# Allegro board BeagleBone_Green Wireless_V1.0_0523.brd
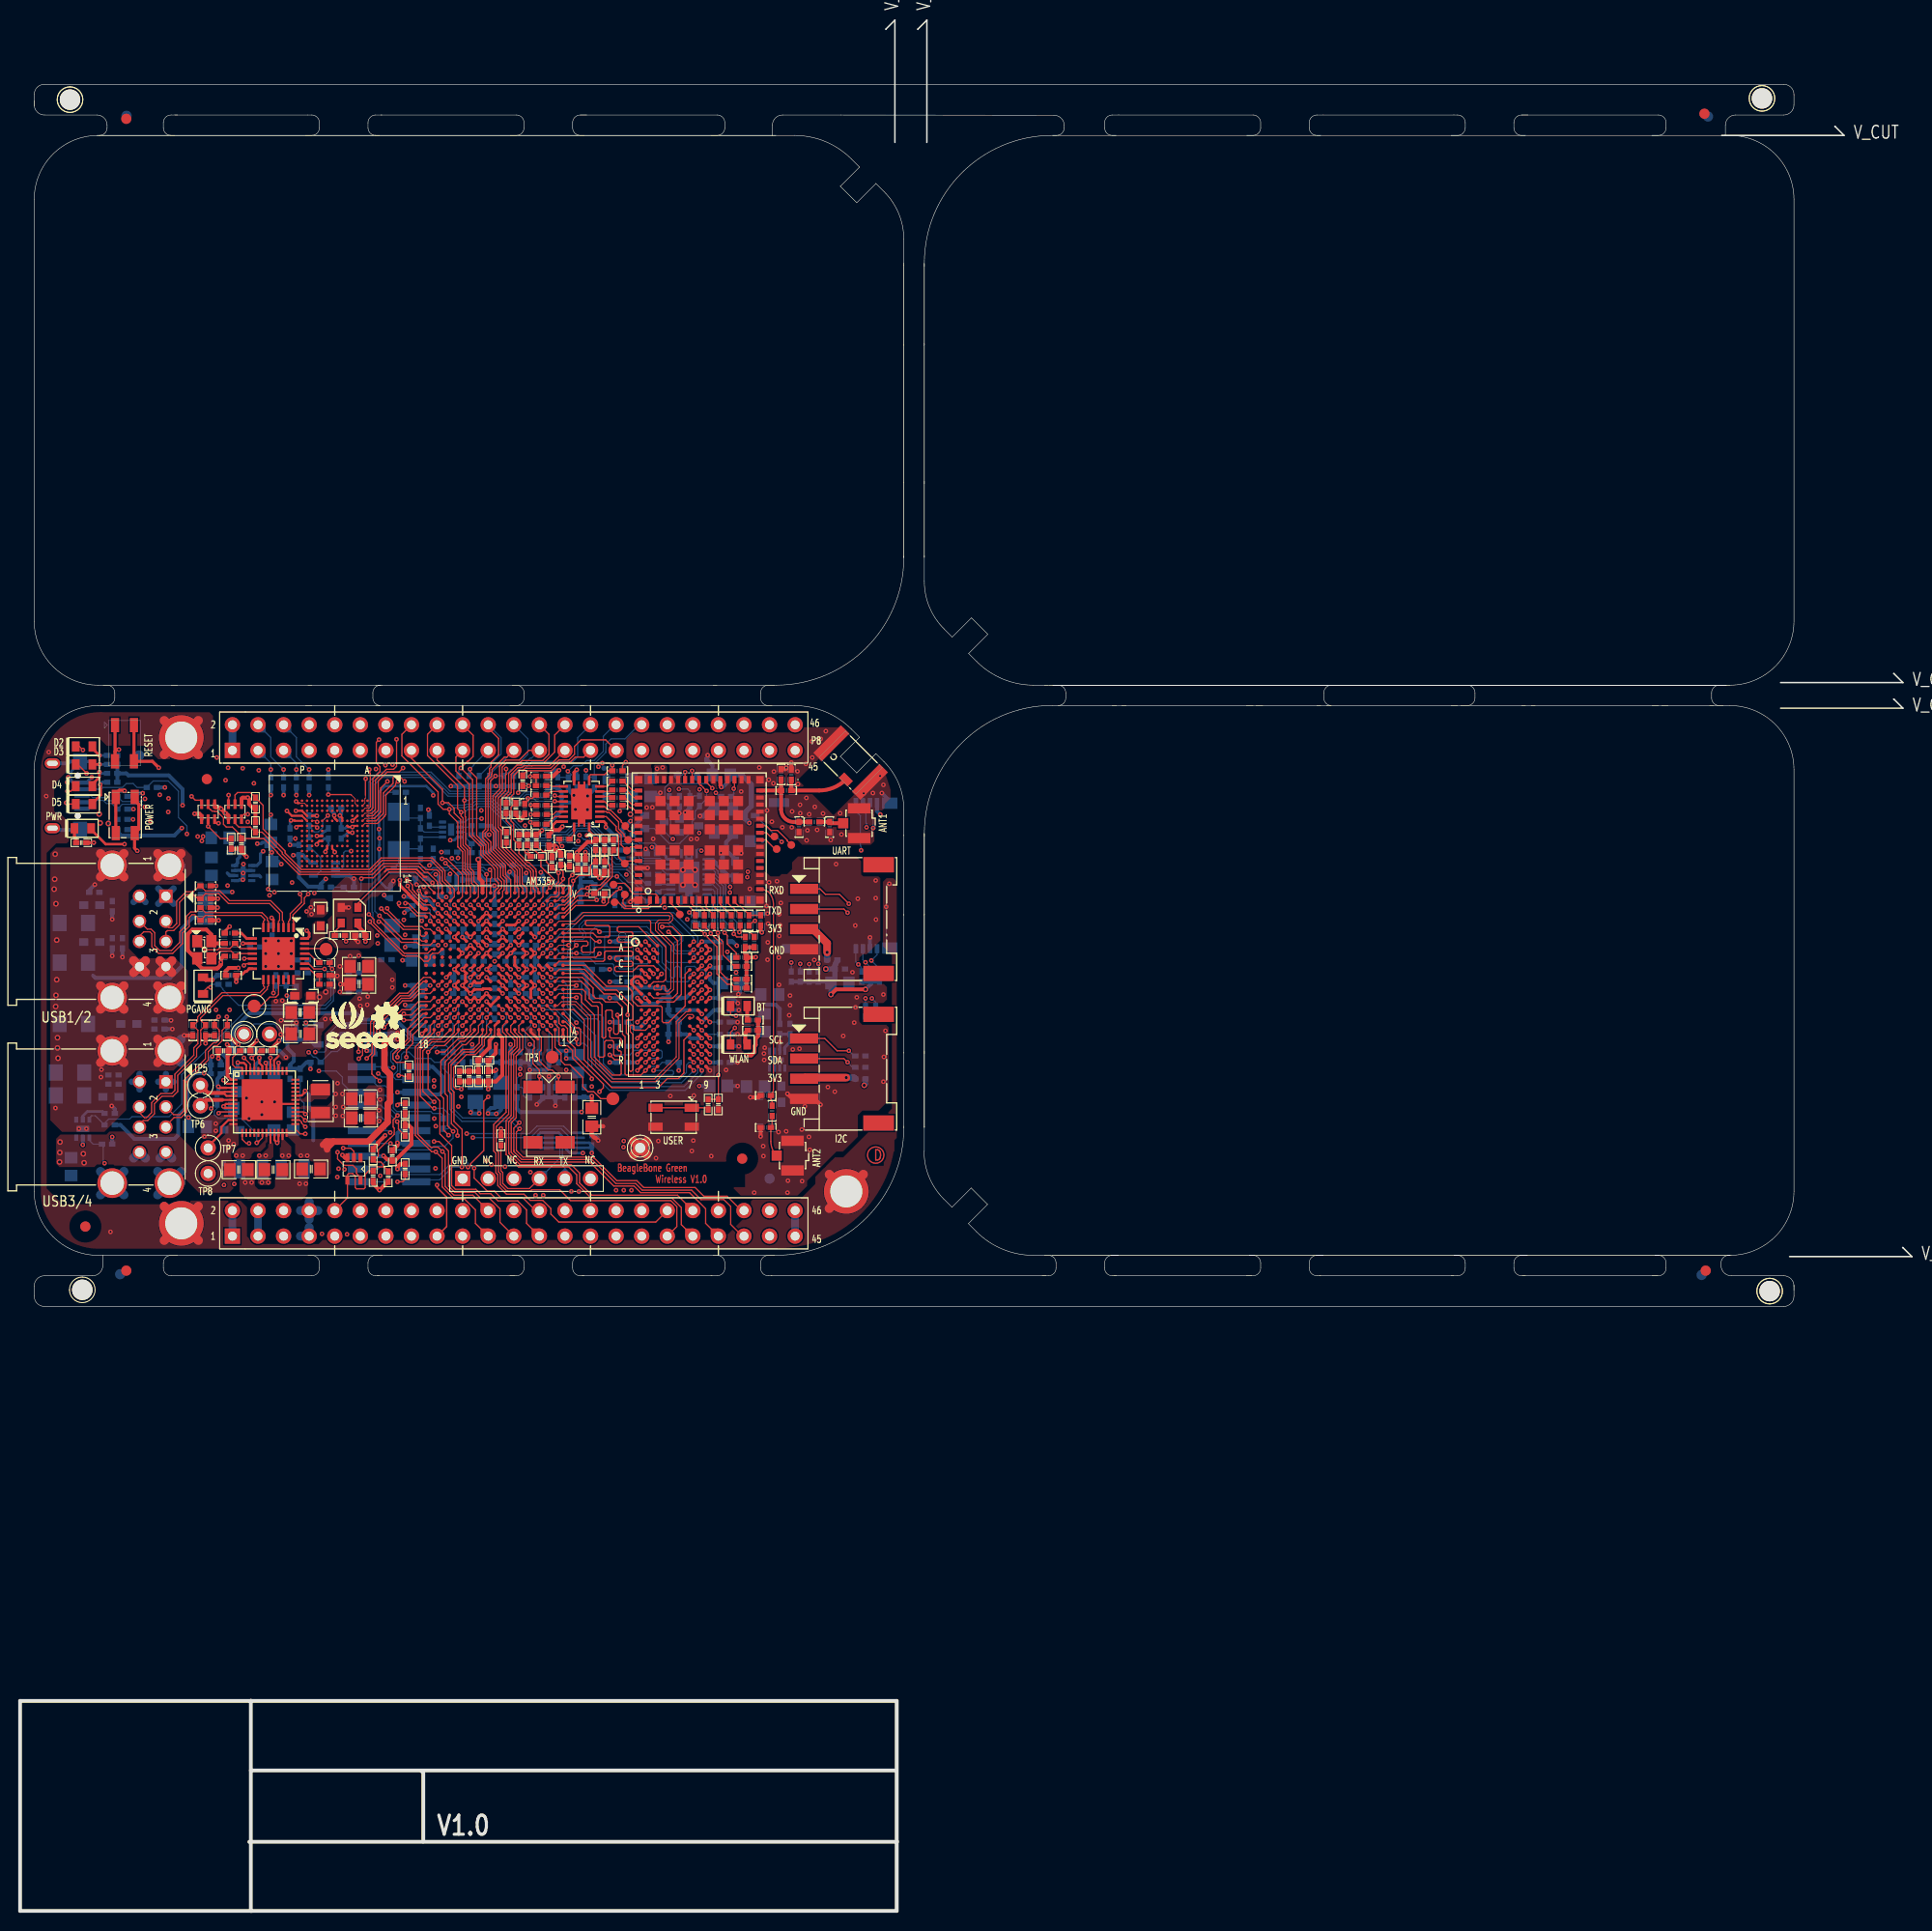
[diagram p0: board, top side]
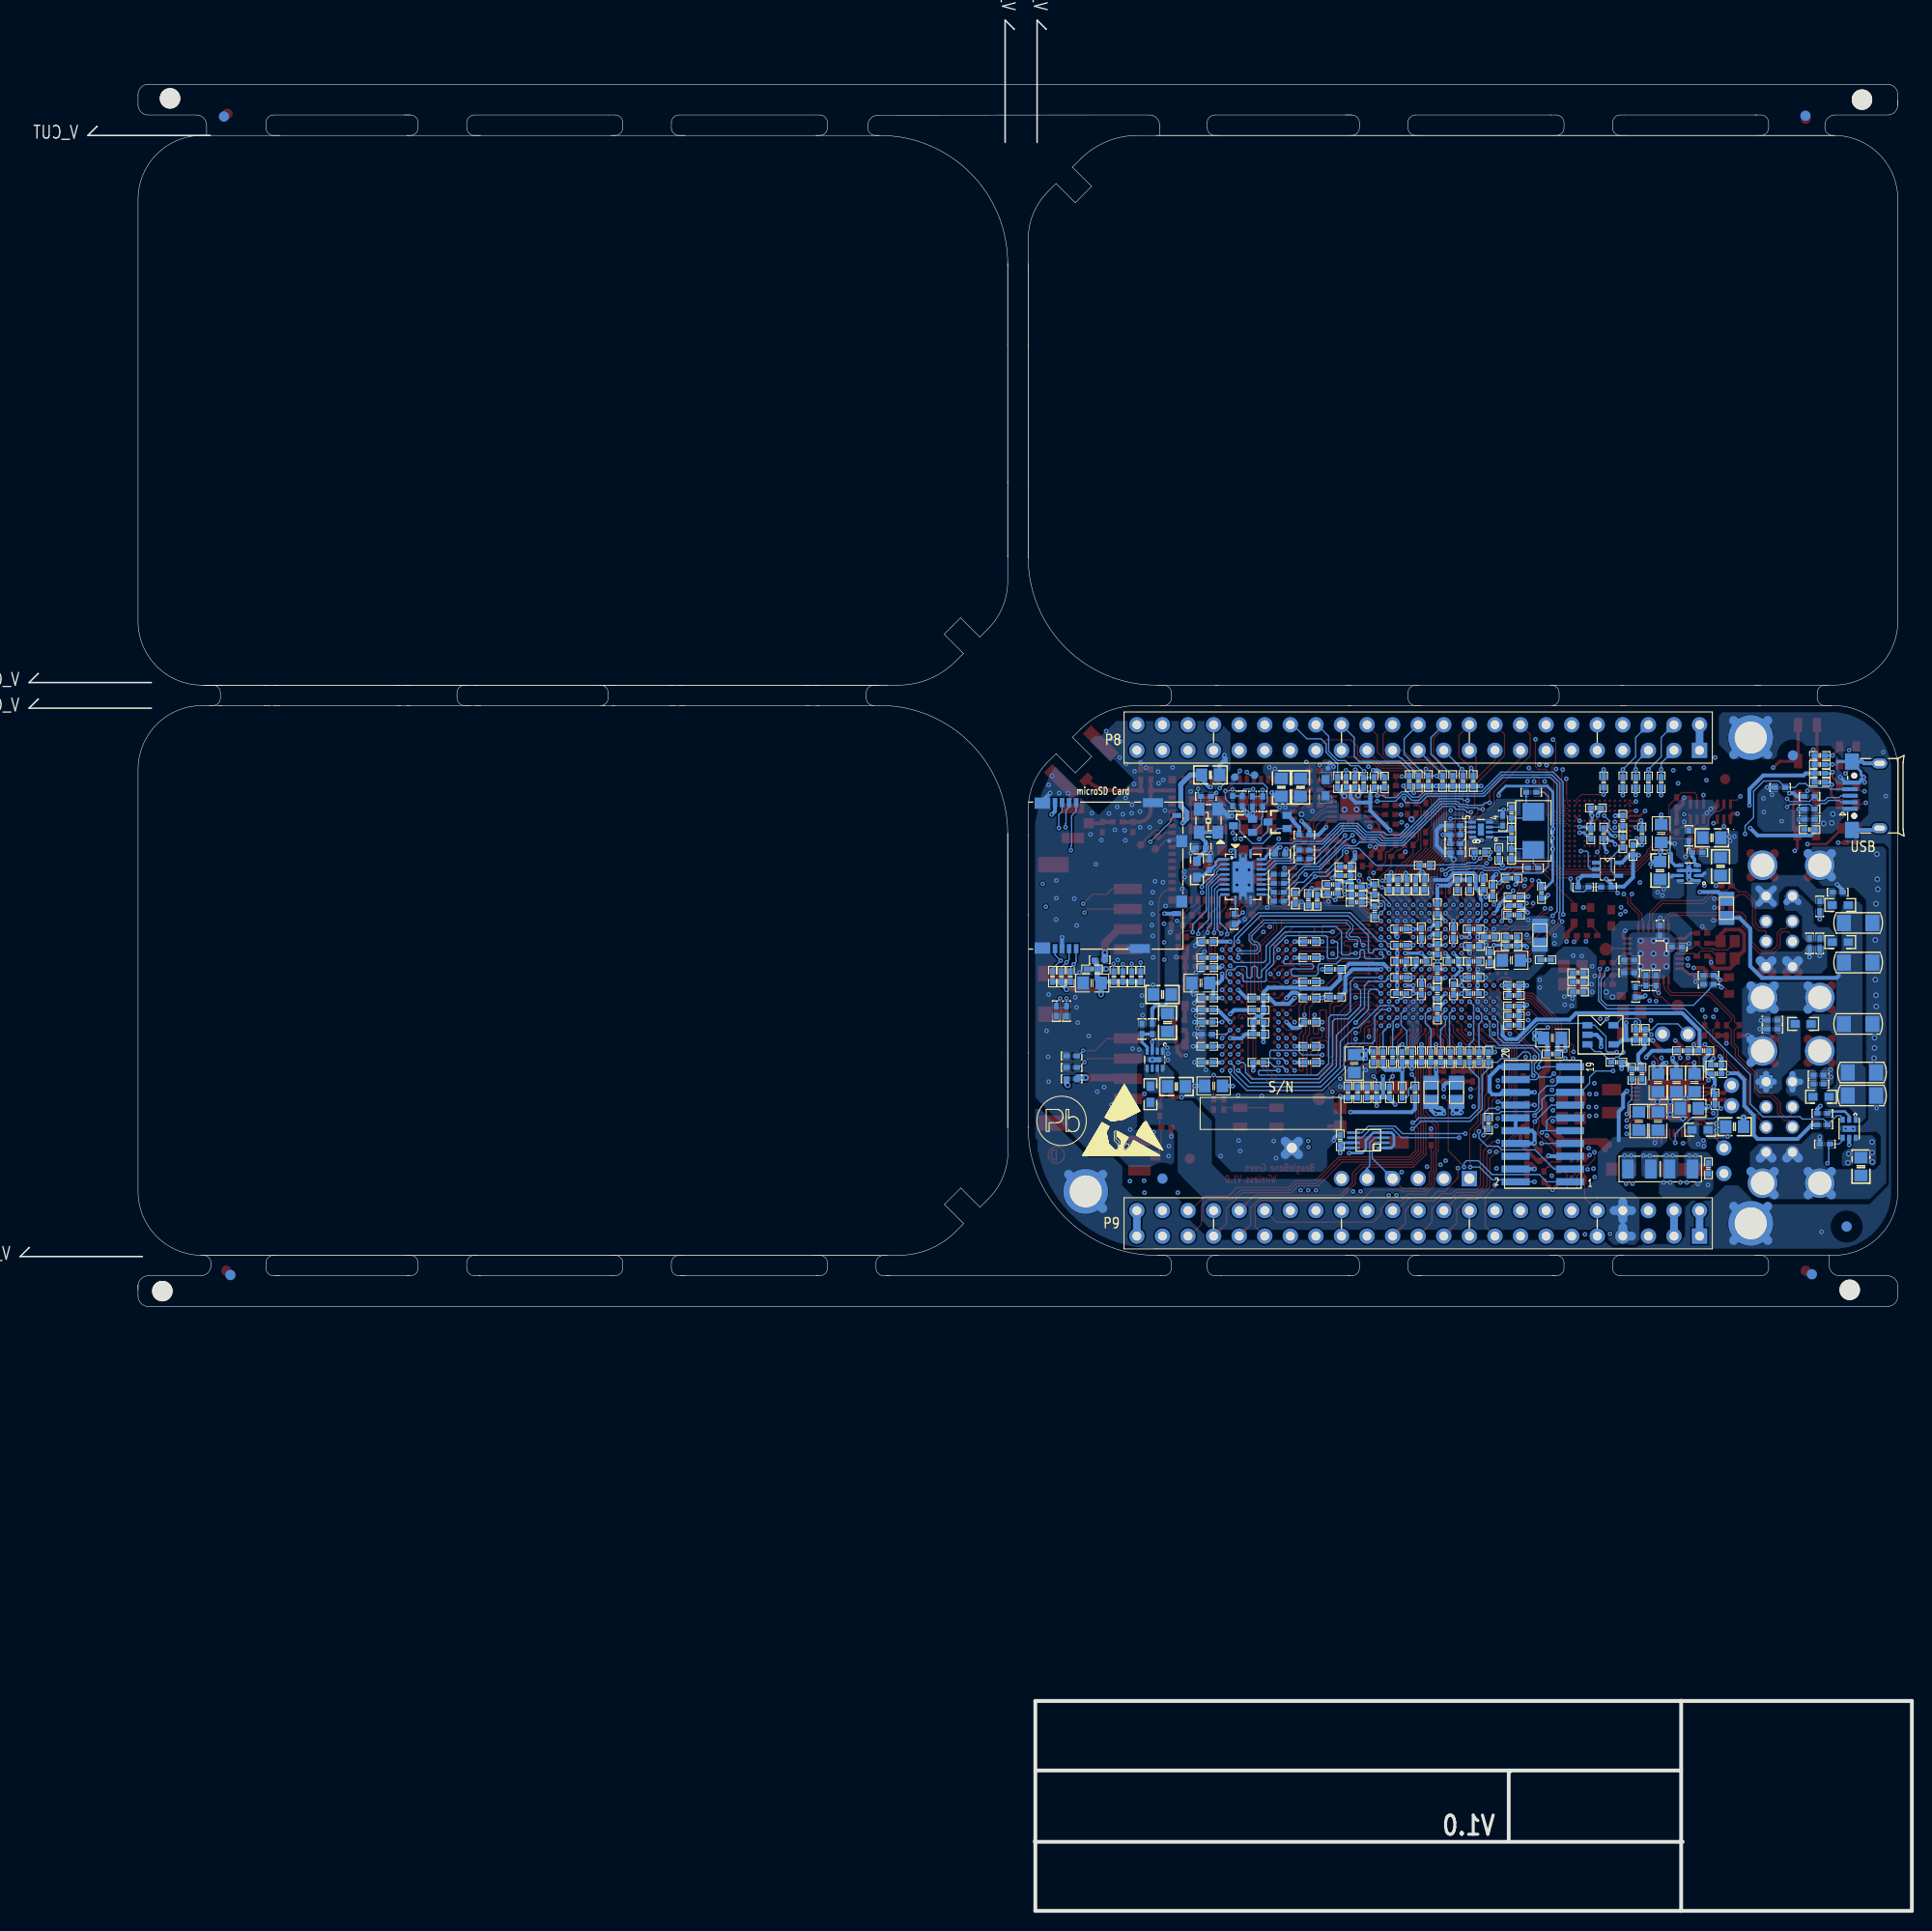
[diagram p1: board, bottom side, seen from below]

Outline 187.86 x 187.83 mm; copper layers: TOP, LYR2_GND, LYR3, LYR4, LYR5_PWR, BOTTOM. Coordinates in mm from the lower left corner of the outline.

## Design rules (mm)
net group HUB_D1: nets HUB_DM1 HUB_DP1
net group HUB_D2: nets HUB_DM2 HUB_DP2
net group HUB_D3: nets HUB_DM3 HUB_DP3
net group HUB_D4: nets HUB_DM4 HUB_DP4
net group USB0: nets USB0_DM USB0_DP
net group USB1: nets USB1_DM USB1_DP
net group CLK: nets MMC0_CLKO
net group DDR_ADD: nets DDR_A0 DDR_A1 DDR_A2 DDR_A3 DDR_A4 DDR_A5 DDR_A6 DDR_A7 DDR_A8 DDR_A9 DDR_A10 DDR_A11 DDR_A12 DDR_A13 DDR_A14 DDR_BA0 DDR_BA1 DDR_BA2 DDR_CASN DDR_CKE DDR_CLK DDR_CLKN DDR_CSN DDR_ODT DDR_RASN DDR_WEN
net group DDR_DQ0: nets DDR_D0 DDR_D1 DDR_D2 DDR_D3 DDR_D4 DDR_D5 DDR_D6 DDR_D7 DDR_DQM0 DDR_DQS0 DDR_DQSN0
net group DDR_DQ1: nets DDR_D8 DDR_D9 DDR_D10 DDR_D11 DDR_D12 DDR_D13 DDR_D14 DDR_D15 DDR_DQM1 DDR_DQS1 DDR_DQSN1
nets with their own width: min track width 0.203; nets USB1_VBUS

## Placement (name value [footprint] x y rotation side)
ANT  ACA-5036-A2-CC-S  [ACA5036]  82.47 114.08 225 top
C1  10uF,10V  [805]  21.72 73.63 180 top
C2  10uF,10V  [805]  17.6 77.9 0 bottom
C3  0.1uf,16V  [402]  22.35 85.45 180 top
C4  10uF,10V  [805]  21.59 82.27 90 bottom
C7  10uF,10V  [805]  25.21 78.46 270 bottom
C8  10uF,10V  [805]  27.11 78.46 270 bottom
C9  10uF,10V  [805]  25.15 73.63 180 top
C10  10uF,10V  [805]  22.1 79.73 180 bottom
C11  10uF,10V  [805]  33.83 78.77 180 top
C12  10uF,10V  [805]  28.89 73.7 0 top
C13  10uF,10V  [805]  25.21 82.27 90 bottom
C14  10uF,10V  [805]  27.81 87.12 0 top
C15  10uF,10V  [805]  23.37 82.27 90 bottom
C16  2.2uF,6.3V  [402]  19.43 84.05 0 bottom
C18  2.2uF,6.3V  [402]  20.19 85.45 180 top
C21  18pF,50V  [402]  51.88 81.32 90 bottom
C22  18pF,50V  [402]  53.15 81.32 90 bottom
C24  2.2uF,6.3V  [402]  35.05 73 270 top
C25  18pF,50V  [402]  39.75 105 270 bottom
C26  18pF,50V  [402]  39.75 109.07 90 bottom
C28  0.1uf,16V  [402]  57.28 93.54 0 bottom
C29  0.1uf,16V  [402]  36.96 75.03 90 top
C30  0.1uf,16V  [402]  36.55 72.95 270 top
C31  0.1uf,16V  [402]  44.58 82.91 270 top
C32  0.001uf,50V  [402]  43.62 82.91 270 top
C33  0.1uf,16V  [402]  45.53 82.91 270 top
C36  0.1uf,16V  [402]  10.16 107.42 0 bottom
C37  0.1uf,16V  [402]  26.8 83.16 270 bottom
C38  0.1uf,16V  [402]  39.75 96.75 180 bottom
C39  10uF,10V  [805]  33.66 93.83 0 top
C40  10uF,10V  [805]  33.66 92.05 0 top
C41  0.1uf,16V  [402]  43.52 97.54 180 bottom
C42  0.1uf,16V  [402]  47.12 97.54 270 bottom
C43  0.1uf,16V  [402]  48.72 97.14 90 bottom
C44  0.1uf,16V  [402]  39.52 90.94 180 bottom
C45  0.1uf,16V  [402]  39.75 95.86 180 bottom
C46  0.1uf,16V  [402]  45.52 94.34 0 bottom
C47  0.1uf,16V  [402]  47.12 95.54 270 bottom
C48  0.1uf,16V  [402]  48.72 94.34 0 bottom
C49  0.1uf,16V  [402]  47.12 93.14 90 bottom
C50  0.1uf,16V  [402]  48.72 91.54 90 bottom
C51  0.1uf,16V  [402]  33.15 93.19 180 bottom
C52  0.1uf,16V  [402]  33.15 92.3 180 bottom
C53  0.1uf,16V  [402]  33.15 91.29 180 bottom
C54  0.1uf,16V  [402]  39.52 91.94 180 bottom
C55  10uF,10V  [805]  33.83 80.67 180 top
C56  0.1uf,16V  [402]  47.12 99.54 270 bottom
C57  0.1uf,16V  [402]  55.3 112.12 270 bottom
C58  0.1uf,16V  [402]  43.92 101.94 90 bottom
C59  0.1uf,16V  [402]  44.89 84.81 270 bottom
C60  0.1uf,16V  [402]  43.52 92.74 180 bottom
C61  0.1uf,16V  [402]  56.26 102.84 180 bottom
C62  10uF,10V  [805]  35.69 86.72 0 bottom
C63  0.1uf,16V  [402]  45.52 91.54 90 bottom
C64  0.1uf,16V  [402]  35.69 85.13 180 bottom
C65  0.1uf,16V  [402]  43.52 94.34 180 bottom
C66  0.1uf,16V  [402]  43.48 95.81 180 bottom
C67  0.1uf,16V  [402]  41.91 94.72 90 bottom
C68  0.1uf,16V  [402]  50.16 101.96 270 bottom
C69  0.1uf,16V  [402]  36.78 101.12 270 bottom
C70  0.1uf,16V  [402]  43.52 91.14 180 bottom
C71  0.1uf,16V  [402]  39.75 102.59 180 bottom
C72  0.1uf,16V  [402]  47.12 91.14 270 bottom
C73  0.1uf,16V  [402]  50.72 97.54 0 bottom
C74  0.1uf,16V  [402]  51.92 101.94 270 bottom
C75  0.1uf,16V  [402]  52.37 112.09 270 bottom
C76  0.1uf,16V  [402]  51.05 101.96 270 bottom
C77  10uF,10V  [805]  39.78 94.44 180 bottom
C78  0.1uf,16V  [402]  39.5 98.93 0 bottom
C79  0.1uf,16V  [402]  36.37 94.49 180 bottom
C80  0.1uf,16V  [402]  42.59 101.96 90 bottom
C81  0.1uf,16V  [402]  49.28 101.96 90 bottom
C82  0.1uf,16V  [402]  39.52 89.89 180 bottom
C83  0.1uf,16V  [402]  39.52 88.94 180 bottom
C84  0.1uf,16V  [402]  48.39 101.96 90 bottom
C85  0.1uf,16V  [402]  39.52 87.99 180 bottom
C86  0.1uf,16V  [402]  39.47 100.74 180 bottom
C87  0.1uf,16V  [402]  41.96 96.75 0 bottom
C88  0.1uf,16V  [402]  47.12 89.13 270 bottom
C89  1uF,10V  [402]  47.75 84.81 270 bottom
C90  1uF,10V  [402]  45.85 84.81 270 bottom
C91  1uF,10V  [402]  46.8 84.81 270 bottom
C92  0.1uf,16V  [402]  49.66 84.81 270 bottom
C93  0.1uf,16V  [402]  46.48 82.91 270 top
C94  0.1uf,16V  [402]  45.52 97.14 270 bottom
C95  10uF,10V  [805]  55.37 84.18 90 bottom
C96  10uF,10V  [805]  56.77 78.84 90 top
C97  0.1uf,16V  [402]  50.72 95.94 180 bottom
C98  0.1uf,16V  [402]  50.72 94.34 180 bottom
C99  0.1uf,16V  [402]  50.72 92.74 180 bottom
C100  0.1uf,16V  [402]  50.72 91.14 180 bottom
C101  0.1uf,16V  [402]  53.47 84.81 270 bottom
C102  0.1uf,16V  [402]  55.05 81.32 90 bottom
C103  0.1uf,16V  [402]  56.01 81.32 90 bottom
C104  1uF,10V  [402]  50.61 84.81 270 bottom
C105  0.1uf,16V  [402]  48.7 84.81 270 bottom
C106  1uF,10V  [402]  45.12 101.94 90 bottom
C107  0.1uf,16V  [402]  59.82 96.29 180 bottom
C108  0.1uf,16V  [402]  59.82 94.69 180 bottom
C109  0.1uf,16V  [402]  59.82 92.29 180 bottom
C110  0.1uf,16V  [402]  59.82 90.69 180 bottom
C111  0.1uf,16V  [402]  59.82 88.29 180 bottom
C112  0.1uf,16V  [402]  59.82 85.89 180 bottom
C113  0.1uf,16V  [402]  59.82 84.29 180 bottom
C114  0.1uf,16V  [402]  69.98 96.29 0 bottom
C115  0.1uf,16V  [402]  69.98 94.69 0 bottom
C116  0.1uf,16V  [402]  69.98 93.7 0 bottom
C117  0.1uf,16V  [402]  69.98 90.69 0 bottom
C118  10uF,10V  [805]  70.61 92.18 180 bottom
C119  0.1uf,16V  [402]  69.98 89.49 0 bottom
C120  0.1uf,16V  [402]  69.98 85.89 0 bottom
C121  0.1uf,16V  [402]  69.98 84.29 0 bottom
C122  10uF,10V  [805]  69.34 81.95 180 bottom
C123  0.001uf,50V  [402]  64.9 89.49 0 bottom
C124  0.1uf,16V  [402]  64.9 87.09 180 bottom
C125  2.2uF,6.3V  [402]  30.61 112.12 90 bottom
C126  10uF,10V  [805]  24.89 107.04 90 bottom
C127  0.1uf,16V  [402]  26.8 107.04 270 bottom
C128  0.1uf,16V  [402]  30.61 107.04 90 bottom
C129  0.1uf,16V  [402]  31.88 107.04 270 bottom
C130  0.1uf,16V  [402]  31.37 109.58 180 bottom
C152  0.1uf,16V  [402]  27.43 87.03 90 bottom
C153  10uF,10V  [805]  81.41 92.18 0 bottom
C154  0.1uf,16V  [402]  81.41 93.57 0 bottom
C155  0.1uf,16V  [402]  56.77 76.56 270 bottom
C158  0.1uf,16V  [402]  27.69 105.38 90 bottom
C159  0.1uf,16V  [402]  33.78 96.9 180 top
C167  0.1uf,16V  [402]  70.61 105.64 0 bottom
C168  10uF,10V  [805]  69.65 112.85 0 bottom
C169  10uF,10V  [805]  60.71 111.61 90 bottom
C170  10uF,10V  [805]  62.61 111.61 90 bottom
C171  10pF  [402]  78.87 108.18 0 top
C172  10pF  [402]  74.68 79.48 270 top
C173  0.1uf,16V  [402]  60.32 106.88 0 bottom
C174  0.1uf,16V  [402]  69.75 103.94 90 bottom
C175  0.1uf,16V  [402]  52.5 106.35 90 top
C176  0.1uf,16V  [402]  62.74 105 0 bottom
C177  10uF,10V  [805]  73.03 81.89 0 bottom
C178  22uF,10V  [805]  74.42 91.03 180 bottom
C179  22uF,10V  [805]  19.86 106.6 180 bottom
C180  10uF,10V  [805]  25.02 103.35 270 bottom
C181  0.1uf,16V  [402]  25.02 97.38 270 bottom
C182  0.1uf,16V  [402]  23.34 95.76 0 bottom
C183  18pF,50V  [402]  20.83 96.11 180 top
C184  18pF,50V  [402]  20.83 94.84 180 top
C185  0.1uf,16V  [402]  28.07 94.46 180 bottom
C186  0.1uf,16V  [402]  20.95 92.94 0 top
C187  0.1uf,16V  [402]  28.07 93.19 180 bottom
C188  10uF,10V  [805]  27.81 89.26 180 top
C189  0.1uf,16V  [402]  7.37 101.19 180 bottom
C190  100uF  [1206]  5.33 98.15 180 bottom
C191  0.1uf,16V  [402]  9.14 96.11 270 bottom
C192  100uF  [1206]  5.33 94.21 180 bottom
C193  0.1uf,16V  [402]  13.84 88.49 0 bottom
C194  100uF  [1206]  5.33 88.11 180 bottom
C195  0.1uf,16V  [402]  9.27 82.14 180 bottom
C196  100uF  [1206]  4.95 83.29 180 bottom
C197  10uF,10V  [805]  5.05 73.94 270 bottom
C198  100uF  [1206]  4.95 81 180 bottom
C199  1uF,10V  [402]  25.4 92.43 90 bottom
C200  10pF  [402]  76.07 111.3 0 top
C202  100pF  [402]  83.44 84.94 0 bottom
C203  100pF  [402]  83.44 83.79 0 bottom
C204  100pF  [402]  84.96 89.38 270 bottom
C205  100pF  [402]  83.95 89.38 270 bottom
D1  GREEN  [LED_0603]  6.22 107.54 0 top
D2  LTST-C191TBKT  [LED_0603]  6.35 115.67 0 top
D3  LTST-C191TBKT  [LED_0603]  6.35 113.89 0 top
D4  LTST-C191TBKT  [LED_0603]  6.35 111.73 0 top
D5  LTST-C191TBKT  [LED_0603]  6.35 109.96 0 top
D6  GREEN  [LED_0603]  18.16 91.92 90 top
D7  GREEN  [LED_0603]  71.37 89.89 0 top
D8  LTST-C191TBKT  [LED_0603]  71.37 86.08 0 top
D9  ESDPSA0402V05  [402]  9.14 99.8 270 bottom
D10  ESDPSA0402V05  [402]  18.41 100.56 0 top
D11  ESDPSA0402V05  [402]  18.41 101.83 0 top
D12  ESDPSA0402V05  [402]  10.16 96.11 90 bottom
D13  ESDPSA0402V05  [402]  18.41 98.4 180 top
D14  ESDPSA0402V05  [402]  18.41 99.67 180 top
D15  ESDPSA0402V05  [402]  13.84 87.6 0 bottom
D16  ESDPSA0402V05  [402]  20.57 87.48 270 top
D17  ESDPSA0402V05  [402]  19.3 87.48 270 top
D18  ESDPSA0402V05  [402]  9.27 83.03 0 bottom
D19  ESDPSA0402V05  [402]  18.41 87.48 90 top
D20  ESDPSA0402V05  [402]  17.14 87.48 90 top
D21  ESDPSA0402V05  [402]  10.16 109.45 180 bottom
D22  ESDPSA0402V05  [402]  10.16 110.72 180 bottom
D23  ESDPSA0402V05  [402]  13.08 111.61 180 bottom
D24  ESDPSA0402V05  [402]  10.16 108.43 180 bottom
FB1  150OHM800mA  [SM-7351-IND-0805]  36.93 96.93 270 bottom
FB2  150OHM800mA  [SM-7351-IND-0805]  47.75 81.32 270 bottom
FB3  150OHM800mA  [SM-7351-IND-0805]  45.21 81.32 270 bottom
FB8  0.1R,0805  [SM-7351-IND-0805]  18.41 99.59 270 bottom
J1  HEADER 6  [SIP6]  43.94 72.75 90 top
J4  GroveHDR  [4P-SMD-2_0-90D]  77.85 83.67 270 top
J5  GroveHDR  [4P-SMD-2_0-90D]  77.85 98.53 270 top
J6  SMD Female U-FL  [U-FL3P-SMD-2_6X2_6X1_0MM]  83.31 108.05 180 top
J7  SMD Female U-FL  [U-FL3P-SMD-2_6X2_6X1_0MM]  76.71 75.03 180 top
J8  -  [ST-USB-201C]  9.14 97.31 90 top
J9  -  [ST-USB-201C]  9.14 78.87 90 top
L1  LQM2HPN2R2MG0L  [2520]  22.92 73.7 180 bottom
L2  LQM2HPN2R2MG0L  [2520]  27.05 73.7 0 bottom
L3  LQM2HPN2R2MG0L  [2520]  29.82 80.44 270 top
L4  BLM18KG221SN1D  [603]  70.99 103.48 270 bottom
L7  DNP  [402]  77.34 107.67 90 top
L8  DNP  [402]  80.39 107.67 90 top
L9  DNP  [402]  74.04 81 0 top
L10  DNP  [402]  74.04 77.83 0 top
L11  0.47uH  [805]  73.91 88.24 90 bottom
L12  0.33uH  [805]  19 103.76 90 bottom
L13  BLM18KG221SN1D  [603]  75.62 81.13 90 bottom
L14  BLM18KG221SN1D  [603]  58.22 111.58 270 bottom
L15  BLM18KG221SN1D  [603]  28.07 90.91 0 top
L16  BLM18KG221SN1D  [603]  29.84 98.65 90 top
L17  BLM18KG221SN1D  [603]  10.79 88.11 180 bottom
L18  BLM18KG221SN1D  [603]  9.02 80.87 180 bottom
L19  BLM18KG221SN1D  [603]  7.11 99.92 180 bottom
L20  BLM18KG221SN1D  [603]  7.11 96.24 180 bottom
L21  DNP  [402]  75.57 112.9 270 top
L22  DNP  [402]  76.58 112.88 270 top
MTG1  MHOLE  [MTGH200C125D_PL]  16 68.3 90 top
MTG3  MHOLE  [MTGH200C125D_PL]  16 116.56 90 top
MTG4  MHOLE  [MTGH200C125D_PL]  82.04 71.48 90 top
NOREF  -  [unnamed]  167.39 63.6 270 top
NOREF#2  -  [#2]  82.04 71.48 0 top
NOREF#3  -  [unnamed]  10.54 178.03 270 top
NOREF#4  -  [unnamed#3]  6.17 61.7 0 top
NOREF#5  -  [#2]  83.31 117.2 0 top
NOREF#6  -  [#2]  87.12 93.7 0 top
NOREF#7  -  [#2]  16 68.3 0 top
NOREF#8  -  [#2]  87.76 93.07 0 top
NOREF#9  -  [unnamed]  6.48 67.98 270 top
NOREF#10  -  [unnamed]  18.54 112.43 270 top
NOREF#11  -  [#2]  1.4 65.13 0 top
NOREF#12  -  [unnamed]  167.26 178.54 270 top
NOREF#13  -  [#2]  -10.57 65.13 90 top
NOREF#14  -  [unnamed#3]  4.95 179.93 180 top
NOREF#15  -  [#2]  -366.77 -191.34 0 top
NOREF#16  -  [#2]  7.75 119.74 0 top
NOREF#17  -  [#2]  87.12 104.18 0 top
NOREF#18  -  [unnamed]  10.54 63.6 270 top
NOREF#19  -  [#2]  1.4 53.16 0 top
NOREF#20  -  [#2]  16 68.3 0 top
NOREF#21  -  [#2]  87.76 104.81 0 top
NOREF#22  -  [unnamed#3]  173.74 61.57 0 top
NOREF#23  -  [#2]  41.78 108.43 0 top
NOREF#24  -  [#2]  82.04 71.48 0 top
NOREF#25  -  [#2]  82.04 113.39 0 top
NOREF#26  -  [unnamed]  71.7 74.73 270 top
NOREF#27  -  [#2]  1.4 65.13 0 top
NOREF#28  -  [#2]  -366.9 -191.41 0 top
NOREF#29  -  [#2]  87.76 77.83 0 top
NOREF#30  -  [#2]  87.12 93.7 0 top
NOREF#31  -  [unnamed#3]  172.97 180.06 180 top
NOREF#32  -  [#2]  16 116.56 0 top
NOREF#33  -  [#2]  3.3 118.47 180 bottom
NOREF#34  -  [unnamed]  166.98 63.17 270 bottom
NOREF#35  -  [unnamed]  10.57 178.33 90 bottom
NOREF#36  -  [unnamed]  9.93 63.25 270 bottom
NOREF#37  -  [unnamed]  74.42 72.75 270 bottom
NOREF#38  -  [unnamed]  6.48 67.98 270 bottom
NOREF#39  -  [unnamed]  167.61 178.26 90 bottom
NOREF#40  -  [unnamed]  11.81 114.78 270 bottom
OSC1  7XZ-32.768KHz  [X4-SMD-3_2X2_5X1_0MM]  69.85 108.31 90 bottom
P2  CTI JTAG,DNI  [HEADER10X2_SMD]  36.64 78.14 90 bottom
P4  SMD Micro USB-B-without POST-W/P  [5P-USB-B]  6.38 110.78 90 bottom
P8  FEMALE HEADER 2x23  [HEADER23X2]  21.08 115.29 0 top
P9  FEMALE HEADER 2x23  [HEADER23X2]  21.08 67.03 0 top
P10  SCHA5B0200  [SD-MICRO-SCHA5B0300]  82.99 102.84 270 bottom
Q1  DMC56404  [SMINI6-F3-B]  21.34 109.19 180 top
Q2  DMC56404  [SMINI6-F3-B]  18.67 109.19 180 top
Q3  BSS138W-7-F  [SOT-323-3]  62.99 108.18 90 bottom
Q4  BSS138W-7-F  [SOT-323-3]  66.42 107.8 90 bottom
R1  100K,1%  [402]  24.51 85.45 180 top
R3  1.5K,1%  [402]  27.81 83.16 270 bottom
R4  1.5K,1%  [402]  29.34 84.3 0 bottom
R5  0R,1%  [402]  19.43 83.16 180 bottom
R6  0R,1%  [402]  20.19 73.76 270 bottom
R7  0R,1%  [402]  19.56 80.62 270 bottom
R8  0R,1%  [402]  20.7 85.45 0 bottom
R9  0R,1% DNP  [402]  22.73 85.45 0 bottom
R12  1.5K,5%  [402]  6.07 106.12 180 top
R14  10K,1%  [402]  35.05 75.16 270 top
R17  1M,1%  [402]  39.75 107.04 90 bottom
R18  33R,5%  [0402]  42.04 78.21 90 bottom
R19  0R,1%  [402]  42.99 84.81 270 bottom
R20  0R,1%  [402]  43.94 84.81 90 bottom
R22  49.9,1%  [402]  57.28 90.78 180 bottom
R23  4.75K,1%  [402]  38.23 77.51 270 top
R24  4.75K,1%  [402]  38.23 79.73 90 top
R25  4.75K,1%  [402]  38.23 73.7 90 top
R26  4.75K,1%  [402]  51.56 84.81 90 bottom
R27  0R,1%  [402]  46.01 84.49 180 top
R29  0R,1%  [402]  41.02 105 90 bottom
R30  0R,1%  [402]  54.1 81.32 270 bottom
R45  22R,5%  [0402]  48.29 106.65 90 top
R46  0R,1%  [0402]  48.26 109.55 90 top
R47  0R,1%  [0402]  49.91 112.27 90 top
R48  0R,1%  [0402]  49.91 112.24 90 bottom
R49  0R,1%  [402]  39.47 99.87 0 bottom
R50  0R,1%  [402]  38.61 83.41 90 top
R51  0R,1%  [402]  42.04 84.81 90 bottom
R54  10K,1%  [402]  52.51 84.81 90 bottom
R55  100K,1%,DNI  [402]  53.39 112.12 90 bottom
R56  100K,1%  [402]  49.53 106.4 270 top
R57  100K,1%,DNI  [402]  50.37 106.4 270 top
R58  100K,1%,DNI  [402]  51.26 106.4 270 top
R59  100K,1%,DNI  [402]  56.18 112.14 90 bottom
R60  100K,1%,DNI  [402]  54.56 104.29 270 top
R61  100K,1%,DNI  [402]  55.37 103.99 270 top
R62  100K,1%,DNI  [402]  57.15 105.89 270 top
R63  100K,1%,DNI  [402]  55.14 101.73 180 bottom
R64  100K,1%,DNI  [402]  55.14 100.2 180 bottom
R65  100K,1%  [402]  58.04 105.89 270 top
R66  100K,1%  [402]  58.93 105.89 270 top
R67  100K,1%  [402]  56.26 103.73 0 bottom
R68  100K,1%  [402]  55.14 100.97 180 bottom
R69  100K,1%,DNI  [402]  57.53 101.07 0 bottom
R70  100K,1%,DNI  [402]  57.53 101.96 0 bottom
R71  4.75K,5%  [402]  9.14 112.12 180 bottom
R72  4.75K,5%  [402]  9.14 114.78 180 bottom
R73  4.75K,5%  [402]  9.14 113.89 180 bottom
R74  4.75K,5%  [402]  9.14 113 180 bottom
R75  100R,1%  [402]  68.33 80.11 270 top
R76  100K,1%  [402]  23.37 107.67 90 top
R77  100K,1%  [402]  23.37 110.08 270 top
R78  100K,1%  [402]  20.95 106.02 270 top
R79  100K,1%  [402]  21.97 106.02 270 top
R80  100K,1%  [402]  54.43 112.09 270 bottom
R81  100K,1%,DNI  [402]  49.23 109.52 270 top
R82  100K,1%  [402]  51.21 104.75 180 top
R83  100K,1%  [402]  52.81 104.17 90 top
R84  100K,1%  [402]  57.02 112.12 270 bottom
R85  100K,1%  [402]  53.7 104.42 90 top
R86  100K,1%  [402]  56.13 103.99 90 top
R87  100K,1%  [402]  57.15 103.73 270 top
R88  100K,1%  [402]  53.34 101.45 90 bottom
R89  100K,1%  [402]  53.34 99.29 270 bottom
R90  100K,1%,DNI  [402]  58.04 103.73 270 top
R91  100K,1%,DNI  [402]  57.53 101.07 0 top
R92  100K,1%,DNI  [402]  61.21 100.56 270 bottom
R93  100K,1%,DNI  [402]  69.34 80.11 270 top
R94  100K,1%  [402]  59.05 100.43 270 bottom
R95  100K,1%  [402]  59.94 100.43 270 bottom
R96  10K,1%  [402]  69.98 88.29 180 bottom
R97  1.5K,1%  [402]  64.9 84.29 180 bottom
R98  10K,1%  [402]  64.9 90.69 180 bottom
R99  240R  [402]  70 87.08 0 bottom
R100  10K,1%  [402]  64.9 88.29 180 bottom
R101  10K,1%  [402]  49.02 112.24 90 bottom
R102  10K,1%  [402]  48.01 112.24 90 bottom
R103  10K,1%  [402]  27.43 112.12 90 bottom
R104  10K,1%  [402]  28.7 112.12 90 bottom
R105  10K,1%  [402]  46.61 112.24 90 bottom
R106  10K,1%  [402]  45.59 112.24 90 bottom
R107  10K,1%  [402]  24.89 112.12 90 bottom
R108  10K,1%  [402]  26.16 112.12 90 bottom
R109  10K,1%  [402]  43.56 112.24 90 bottom
R110  10K,1%  [402]  44.58 112.24 90 bottom
R111  10K,1%  [402]  28.7 108.31 270 bottom
R150  10K,1%  [402]  77.47 92.81 90 bottom
R151  10K,1%  [402]  79.25 92.81 90 bottom
R152  10K,1%  [402]  85.34 92.81 90 bottom
R153  10K,1%  [402]  84.46 92.81 90 bottom
R154  10K,1%  [402]  83.57 92.81 90 bottom
R155  10K,1%  [402]  78.36 92.81 90 bottom
R156  10K,1%  [402]  26.48 87.03 90 bottom
R157  10K,1%  [402]  76.58 92.81 270 bottom
R159  0R,1%  [402]  41.61 101.32 270 bottom
R160  0R,1%  [402]  42.9 105.18 180 bottom
R161  0R,1%  [402]  48.39 103.86 0 bottom
R162  0R,1%  [402]  28.7 106.15 90 bottom
R163  4.75K,1%  [402]  49.34 81.32 90 bottom
R164  4.75K,1%  [402]  50.61 81.32 90 bottom
R165  100K,1%  [402]  47.75 76.56 90 top
R167  33R,5%  [0402]  31.75 96.9 0 top
R168  0R,1% DNP  [603]  21.03 77.6 180 bottom
R169  0R,1% DNP  [402]  30.35 101.7 180 bottom
R170  0R,1% DNP  [402]  32.64 101.7 0 bottom
R171  4.75K,5%,DNP  [402]  40.64 108.31 270 bottom
R172  4.75K,5%,DNP  [402]  45.34 106.91 180 bottom
R173  4.75K,5%,DNP  [402]  45.34 105.13 0 bottom
R174  4.75K,5%,DNP  [402]  45.34 107.8 0 bottom
R175  4.75K,5%.DNP  [402]  45.34 106.02 180 bottom
R176  33R,5%  [402]  72.39 98.4 90 top
R177  33R,5%  [402]  71.5 98.4 90 top
R178  33R,5%  [402]  70.61 98.4 90 top
R179  33R,5%  [402]  69.72 98.4 90 top
R180  33R,5%  [402]  68.83 98.4 90 top
R181  33R,5%  [402]  67.06 98.4 90 top
R182  33R,5%  [402]  67.95 98.4 90 top
R183  33R,5%  [402]  59.31 112.24 0 top
R184  33R,5%  [402]  59.31 111.35 0 top
R185  33R,5%  [402]  59.31 110.59 0 top
R186  33R,5%  [402]  59.31 109.83 0 top
R187  33R,5%  [402]  64.47 110.21 90 bottom
R188  33R,5%  [402]  67.46 110.26 90 bottom
R189  100K  [402]  65.48 110.21 270 bottom
R190  100K  [402]  66.5 110.24 270 bottom
R191  10K,1%  [402]  72.9 96.24 90 top
R192  10K,1%  [402]  72.01 96.24 90 top
R193  10K,1%  [402]  71.63 94.72 180 top
R194  10K,1%  [402]  71.63 93.83 180 top
R195  DNP  [402]  71.63 92.56 180 top
R196  10K,1%  [402]  71.63 91.67 180 top
R197  1.5K,1%  [402]  67.31 98.53 270 bottom
R198  33R,5%  [402]  59.31 113.26 180 top
R199  33R,5%  [402]  51.74 110.85 0 top
R200  33R,5%  [402]  51.74 111.79 0 top
R203  33R,5%  [402]  60.32 105.38 0 bottom
R204  33R,5%  [402]  60.32 104.5 0 bottom
R205  33R,5%  [402]  62.87 102.97 0 bottom
R206  33R,5%  [402]  62.87 102.08 0 bottom
R207  33R,5%  [402]  62.87 101.19 0 bottom
R208  33R,5%  [402]  62.87 100.3 0 bottom
R209  1.5K,1%  [402]  50.11 109.47 270 top
R210  1.5K,1%  [402]  51.74 112.73 0 top
R213  DNP  [402]  70.1 110.72 0 bottom
R214  240K,1%  [402]  75.44 87.6 270 bottom
R215  120K  [402]  76.45 87.6 90 bottom
R216  240K,1%  [402]  21.31 105.13 0 bottom
R217  52.3k  [402]  22.15 106.81 90 bottom
R218  680R,1%  [402]  20.83 97.13 180 top
R219  680R,1%  [402]  20.19 92.94 180 bottom
R220  100K,1%  [402]  20.19 92.05 180 bottom
R221  10K,1%  [402]  8.64 76.17 180 bottom
R222  15K,1%  [402]  8.89 79.22 180 bottom
R223  10K,1%  [402]  8.89 78.08 0 bottom
R224  0R,1%  [402]  30.23 94.21 0 top
R225  10K,1%  [402]  30.23 92.05 0 top
R226  DNP  [402]  30.23 92.94 180 top
R227  10K,1%  [402]  27.43 91.29 270 bottom
R228  47k,1%  [402]  26.42 92.43 270 bottom
R229  680R,1%  [402]  72.77 88.49 180 top
R230  680R,1%  [402]  72.77 87.48 180 top
R231  0R,1%  [402]  83.44 82.65 0 bottom
R232  0R,1%  [402]  80.65 94.46 0 bottom
R233  DNP  [402]  73.53 98.4 90 top
R234  0R,1%  [402]  37.62 103.61 180 bottom
R235  0R,1%  [402]  37.8 111.12 0 bottom
R236  33R,5%  [402]  51.77 109.83 0 top
R237  33R,5%  [402]  51.79 108.92 0 top
R238  33R,5%  [402]  51.77 107.95 0 top
R239  33R,5%  [402]  54.05 106.48 0 top
S1  SMD Button Top  [SW_4P]  10.36 116 270 top
S2  SMD Button Top  [SW_4P]  64.9 78.84 180 top
S3  SMD Button Top  [SW_4P]  10.44 108.86 270 top
TP1  TESTPT1  [TP1-8040]  61.57 75.79 0 top
TP2  TESTPT1  [TP60C_SMD]  58.86 80.68 0 top
TP3  TESTPT1  [TP60C_SMD]  52.83 84.81 0 top
TP4  TESTPT1  [TP1-8040]  22.22 87.1 0 top
TP5  TESTPT1  [TP60C33D]  17.91 82.02 0 top
TP6  TESTPT1  [TP60C33D]  17.91 79.98 0 top
TP7  TESTPT1  [TP60C33D]  18.67 75.79 0 top
TP8  TESTPT1  [TP60C33D]  18.67 73.25 0 top
TP9  TESTPT1  [TP60C33D]  24.76 87.1 0 top
TP10  BT_AUD_IN  [TP30C_SMD]  60.1 107.77 0 top
TP11  BT_AUD_OUT  [TP30C_SMD]  60.38 106.4 0 top
TP12  BT_AUD_FSYNC  [TP30C_SMD]  60.25 105.33 0 top
TP13  BT_AUD_CLK  [TP30C_SMD]  60.05 104.04 0 top
TP14  WL_TX  [TP30C_SMD]  76.58 105.89 0 top
TP15  WL_RX  [TP30C_SMD]  74.9 106.73 0 top
TP16  GPIO_4  [TP30C_SMD]  75.13 105.49 0 top
TP17  GPIO11  [TP30C_SMD]  60.05 100.97 0 top
TP18  GPIO9  [TP30C_SMD]  58.93 101.96 0 top
TP19  GPIO10  [TP30C_SMD]  59.03 100.2 0 top
TP20  GPIO12  [TP30C_SMD]  65.51 98.98 0 top
TP22  BT_UART_DBG  [TP30C_SMD]  65.28 112.83 180 bottom
TP23  WL_UART_DBG  [TP30C_SMD]  67.23 112.62 180 bottom
TP24  HUB_SDA  [TP60C_SMD]  30.38 95.53 0 top
TP25  HUB_SCL  [TP60C_SMD]  23.24 89.89 0 top
U2  TPS65217C  [U_48_RSL]  24.26 80.37 0 top
U3  SN74LVC1G06DCK  [DCK5_2P15X1P4]  30.23 103.48 270 bottom
U5  AM3358BZCZ100  [AM33XX_15X15]  47.12 94.34 180 top
U7  24LC32A  [SOT23-5]  30.92 87.03 270 bottom
U12  MT41K256M16TW-107:P  [BGA96_T9_P8_9X14]  64.9 89.89 0 top
U13  MEM_MNAND_4GB  [BGA153_P14_P5_11P5X13]  31.24 107.04 270 top
U15  SN74LVC2G241  [U_8_DCU]  53.98 76.56 90 bottom
U16  SN74LVC1G07DCK  [DCK5_2P15X1P4]  33.15 73.71 180 top
U17  SSDCI3128AF,DNP  [TDFN8_P5_2P0]  42.8 107.42 90 bottom
U18  WL1835MODGB  [E-13_4X13_3-N100_0_75-TOP]  67.44 106.4 0 top
U19  ETA3410  [DFN2X2-8L]  75.18 84.56 0 bottom
U20  ETA3410  [DFN2X2-8L]  22.15 103.1 90 bottom
U21  TXS0108E  [VQFN-20]  55.75 109.96 90 top
U22  TXS0108E  [VQFN-20]  66.42 102.72 270 bottom
U23  GL852G-QFN28  [QFN-28]  25.65 95.1 270 top
U24  ETA6020D  [DFN2X2-6L]  6.22 77.7 270 bottom
Y1  32.768KHz MC-306  [XTAL4_126-216SMD]  52.51 79.1 270 top
Y2  24MHz  [XTAL150SMD_125X196]  37.59 107.29 270 bottom
Y4  24.576MHZ  [OSC4_61X65LS_79X98SMD]  32.72 98.91 180 top
Y5  12MHz  [OSC4-SMD-2_5X2_0X0_55MM]  18.29 95.48 270 top

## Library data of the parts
ANT = ACA-2012-A1-CC-S
C1 C2 C4 C7-C15 C39 C40 C55 C62 C77 C95 C96 C118 C122 C126 C153 C168-C170 C177-C180 = CAP_10uF_Y5V_10V_10%_0805
C3 C28-C31 C33 C36-C38 C41-C54 C56-C61 C63-C76 C78-C88 C92-C94 C97-C103 C105 C107-C117 C119-C121 C124 C127-C130 C152 C154 C155 C158 C159 C167 C171-C176 C181-C200 C202-C205 = CAP_0.1uF_X5R_6.3V_20% 0201
C16 C18 C125 = CAP_2.2uF_X5R_6.3V_10%_0402
C21 C22 C25 C26 = CAP_18PF_COG_50V_5%_0402
C24 C89-C91 C104 C106 = CAP_1.0UF_X5R_10V_10%_0402
C32 C123 = CAP_0.001_X7R_50V_5%_0402
D1-D8 = LED_LTST-C150GKT_0
D9-D24 = DIODE TVS BI-DIR
FB1-FB3 FB8 = FER_180_200_0
J1 = HEADER 6: User Part Number: ***
J4 J5 = HEADER 4
J6 J7 = Micro RF Coax 3P
J8 J9 = ST-USB-201C
L1-L3 = IND_2.2uH_2.6A_10%_SMD
L4 L7-L22 = INDUCTOR
MTG1 MTG3 MTG4 = MHOLE
OSC1 = Crystal Oscillator
P2 = HDR_10x2_CJTAG_0
P4 = MINI-USB-AB-SOCKET
P8 P9 = HDR_46_F_2_0.1_0.1
P10 = microSD_CONN_8: User Part Number: X; Tolerance: X
Q1 Q2 = RN1907
Q3 Q4 = MOSFET N GSD: User Part Number: *
R1 R55-R70 R75-R95 R165 = RES_100K_1/16W_1%_0402
R3 R4 R168 = RES_1.5K_1/16W_5%_0402
R5-R9 R23-R26 R50 R51 R159-R164 R169 R170 = RES_4.75K_1/16W_1%_0402
R12 R71-R74 R171-R175 = RES_470_1/10W_5%_0402
R14 = RES_10K_1/16W_1%_0402: signal model: 33OHMRESISTOR1_16W5_0402_SM_735_33
R17 = RES_1M_1/16W_1%_0402: signal model: 33OHMRESISTOR1_16W5_0402_SM_735_33
R18 R47 = RES_33_0402: signal model: 33OHMRESISTOR1_16W5_0402_SM_735_33
R19 R27 R29 R30 R156 R234 R235 = RES_0_1/16W_1%_0402
R20 = RES_0_1/16W_1%_0402: signal model: 33OHMRESISTOR1_16W5_0402_SM_735_33
R22 = RES_4.7K_0402
R45 R46 R48 R167 = RES_33_0402
R49 = RES_100K_1/16W_1%_0402: signal model: 33OHMRESISTOR1_16W5_0402_SM_735_33
R54 R96-R111 R150-R155 R157 R176-R200 R203-R210 R213-R233 R236-R239 = RES_10K_1/16W_1%_0402
S1 S3 = SW_KT11P2JM_2
S2 = SW_KT11P2JM_1
TP1-TP20 TP22-TP25 = TESTPT1
U2 = PWR_TPS65217_2
U3 = IC_SN74LVC1G06DCK_0
U5 = IC_AM335X_ZCZ
U7 = MEM_24LC32_SOT23-5
U12 = MT47H256M8_7
U13 = MEM_MNAND_2GB
U15 = IC_SN74LVC2G241_1
U16 = IC_SN74LVC1G07DCK
U17 = SSDCI3128AF
U18 = WL1835MODGB
U19 U20 = ETA3410_0
U21 U22 = TXS0108E_0
U23 = GL852G-QFN28
U24 = ETA6020D
Y1 = CRYS_32_768KHz_SMD32_1
Y2 = CRYS_24MHz_SCC_0
Y4 = OSC_12MHz_1.3V: Tolerance: TOL*; User Part Number: P/N*
Y5 = CRYSTAL4/SM

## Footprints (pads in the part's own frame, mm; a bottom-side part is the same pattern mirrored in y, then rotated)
4P-SMD-2_0-90D
  rect 1.524x3.048 smd: (-5.4,7.4) (5.4,7.4)
  rect 1.016x2.794 smd: 1(-3,0) 2(-1,0) 3(1,0) 4(3,0)
5P-USB-B
  round 0.61 hole 0.61 unplated: (-2,-0.65) (2,-0.65)
  rect 0.406x1.524 smd: 1(-1.3,-0.25) 2(-0.65,-0.25) 3(0,-0.25) 4(0.65,-0.25) 5(1.3,-0.25)
  rect 1.626x1.397 smd: 6(3.4,-0.427) 7(-3.4,-0.427)
  oval 1.016x1.524 hole 0.508x1.067: 8(-3.22,-3.175) 9(3.22,-3.175)
402
  rect 0.635x0.508 smd: 1(-0.508,0) 2(0.508,0)
0402
  rect 0.635x0.508 smd: 1(-0.508,0) 2(0.508,0)
603
  rect 0.914x0.762 smd: 1(-0.8,0) 2(0.8,0)
805
  rect 1.143x1.27 smd: 1(-0.889,0) 2(0.889,0)
1206
  rect 1.397x1.626 smd: 1(-1.41,0) 2(1.41,0)
2520
  rect 1.143x1.905 smd: 1(-1.143,0) 2(1.143,0)
ACA5036
  rect 0.762x1.219 smd: 1(1.525,0.85)
  rect 3.861x1.168 smd: 2(0,2.725) 3(0,-2.725)
AM33XX_15X15
  round 0.356 smd: A1(-6.8,6.8) A2(-6,6.8) A3(-5.2,6.8) A4(-4.4,6.8) A5(-3.6,6.8) A6(-2.8,6.8) A7(-2,6.8) A8(-1.2,6.8) A9(-0.4,6.8) A10(0.4,6.8) A11(1.2,6.8) A12(2,6.8) A13(2.8,6.8) A14(3.6,6.8) A15(4.4,6.8) A16(5.2,6.8) A17(6,6.8) A18(6.8,6.8) B1(-6.8,6) B2(-6,6) B3(-5.2,6) B4(-4.4,6) B5(-3.6,6) B6(-2.8,6) B7(-2,6) B8(-1.2,6) B9(-0.4,6) B10(0.4,6) B11(1.2,6) B12(2,6) B13(2.8,6) B14(3.6,6) B15(4.4,6) B16(5.2,6) B17(6,6) B18(6.8,6) C1(-6.8,5.2) C2(-6,5.2) C3(-5.2,5.2) C4(-4.4,5.2) C5(-3.6,5.2) C6(-2.8,5.2) C7(-2,5.2) C8(-1.2,5.2) C9(-0.4,5.2) C10(0.4,5.2) C11(1.2,5.2) C12(2,5.2) C13(2.8,5.2) C14(3.6,5.2) C15(4.4,5.2) C16(5.2,5.2) C17(6,5.2) C18(6.8,5.2) D1(-6.8,4.4) D2(-6,4.4) D3(-5.2,4.4) D4(-4.4,4.4) D5(-3.6,4.4) D6(-2.8,4.4) D7(-2,4.4) D8(-1.2,4.4) D9(-0.4,4.4) D10(0.4,4.4) D11(1.2,4.4) D12(2,4.4) D13(2.8,4.4) D14(3.6,4.4) D15(4.4,4.4) D16(5.2,4.4) D17(6,4.4) D18(6.8,4.4) E1(-6.8,3.6) E2(-6,3.6) E3(-5.2,3.6) E4(-4.4,3.6) E5(-3.6,3.6) E6(-2.8,3.6) E7(-2,3.6) E8(-1.2,3.6) E9(-0.4,3.6) E10(0.4,3.6) E11(1.2,3.6) E12(2,3.6) E13(2.8,3.6) E14(3.6,3.6) E15(4.4,3.6) E16(5.2,3.6) E17(6,3.6) E18(6.8,3.6) F1(-6.8,2.8) F2(-6,2.8) F3(-5.2,2.8) F4(-4.4,2.8) F5(-3.6,2.8) F6(-2.8,2.8) F7(-2,2.8) F8(-1.2,2.8) F9(-0.4,2.8) F10(0.4,2.8) F11(1.2,2.8) F12(2,2.8) F13(2.8,2.8) F14(3.6,2.8) F15(4.4,2.8) F16(5.2,2.8) F17(6,2.8) F18(6.8,2.8) G1(-6.8,2) G2(-6,2) G3(-5.2,2) G4(-4.4,2) G5(-3.6,2) G6(-2.8,2) G7(-2,2) G8(-1.2,2) G9(-0.4,2) G10(0.4,2) G11(1.2,2) G12(2,2) G13(2.8,2) G14(3.6,2) G15(4.4,2) G16(5.2,2) G17(6,2) G18(6.8,2) H1(-6.8,1.2) H2(-6,1.2) H3(-5.2,1.2) H4(-4.4,1.2) H5(-3.6,1.2) H6(-2.8,1.2) H7(-2,1.2) H8(-1.2,1.2) H9(-0.4,1.2) H10(0.4,1.2) H11(1.2,1.2) H12(2,1.2) H13(2.8,1.2) H14(3.6,1.2) H15(4.4,1.2) H16(5.2,1.2) H17(6,1.2) H18(6.8,1.2) J1(-6.8,0.4) J2(-6,0.4) J3(-5.2,0.4) J4(-4.4,0.4) J5(-3.6,0.4) J6(-2.8,0.4) J7(-2,0.4) J8(-1.2,0.4) J9(-0.4,0.4) J10(0.4,0.4) J11(1.2,0.4) J12(2,0.4) J13(2.8,0.4) J14(3.6,0.4) J15(4.4,0.4) J16(5.2,0.4) J17(6,0.4) J18(6.8,0.4) K1(-6.8,-0.4) K2(-6,-0.4) K3(-5.2,-0.4) K4(-4.4,-0.4) K5(-3.6,-0.4) K6(-2.8,-0.4) K7(-2,-0.4) K8(-1.2,-0.4) K9(-0.4,-0.4) K10(0.4,-0.4) K11(1.2,-0.4) K12(2,-0.4) K13(2.8,-0.4) K14(3.6,-0.4) K15(4.4,-0.4) K16(5.2,-0.4) K17(6,-0.4) K18(6.8,-0.4) L1(-6.8,-1.2) L2(-6,-1.2) L3(-5.2,-1.2) L4(-4.4,-1.2) L5(-3.6,-1.2) L6(-2.8,-1.2) L7(-2,-1.2) L8(-1.2,-1.2) L9(-0.4,-1.2) L10(0.4,-1.2) L11(1.2,-1.2) L12(2,-1.2) L13(2.8,-1.2) L14(3.6,-1.2) L15(4.4,-1.2) L16(5.2,-1.2) L17(6,-1.2) L18(6.8,-1.2) M1(-6.8,-2) M2(-6,-2) M3(-5.2,-2) M4(-4.4,-2) M5(-3.6,-2) M6(-2.8,-2) M7(-2,-2) M8(-1.2,-2) M9(-0.4,-2) M10(0.4,-2) M11(1.2,-2) M12(2,-2) M13(2.8,-2) M14(3.6,-2) M15(4.4,-2) M16(5.2,-2) M17(6,-2) M18(6.8,-2) N1(-6.8,-2.8) N2(-6,-2.8) N3(-5.2,-2.8) N4(-4.4,-2.8) N5(-3.6,-2.8) N6(-2.8,-2.8) N7(-2,-2.8) N8(-1.2,-2.8) N9(-0.4,-2.8) N10(0.4,-2.8) N11(1.2,-2.8) N12(2,-2.8) N13(2.8,-2.8) N14(3.6,-2.8) N15(4.4,-2.8) N16(5.2,-2.8) N17(6,-2.8) N18(6.8,-2.8) P1(-6.8,-3.6) P2(-6,-3.6) P3(-5.2,-3.6) P4(-4.4,-3.6) P5(-3.6,-3.6) P6(-2.8,-3.6) P7(-2,-3.6) P8(-1.2,-3.6) P9(-0.4,-3.6) P10(0.4,-3.6) P11(1.2,-3.6) P12(2,-3.6) P13(2.8,-3.6) P14(3.6,-3.6) P15(4.4,-3.6) P16(5.2,-3.6) P17(6,-3.6) P18(6.8,-3.6) R1(-6.8,-4.4) R2(-6,-4.4) R3(-5.2,-4.4) R4(-4.4,-4.4) R5(-3.6,-4.4) R6(-2.8,-4.4) R7(-2,-4.4) R8(-1.2,-4.4) R9(-0.4,-4.4) R10(0.4,-4.4) R11(1.2,-4.4) R12(2,-4.4) R13(2.8,-4.4) R14(3.6,-4.4) R15(4.4,-4.4) R16(5.2,-4.4) R17(6,-4.4) R18(6.8,-4.4) T1(-6.8,-5.2) T2(-6,-5.2) T3(-5.2,-5.2) T4(-4.4,-5.2) T5(-3.6,-5.2) T6(-2.8,-5.2) T7(-2,-5.2) T8(-1.2,-5.2) T9(-0.4,-5.2) T10(0.4,-5.2) T11(1.2,-5.2) T12(2,-5.2) T13(2.8,-5.2) T14(3.6,-5.2) T15(4.4,-5.2) T16(5.2,-5.2) T17(6,-5.2) T18(6.8,-5.2) U1(-6.8,-6) U2(-6,-6) U3(-5.2,-6) U4(-4.4,-6) U5(-3.6,-6) U6(-2.8,-6) U7(-2,-6) U8(-1.2,-6) U9(-0.4,-6) U10(0.4,-6) U11(1.2,-6) U12(2,-6) U13(2.8,-6) U14(3.6,-6) U15(4.4,-6) U16(5.2,-6) U17(6,-6) U18(6.8,-6) V1(-6.8,-6.8) V2(-6,-6.8) V3(-5.2,-6.8) V4(-4.4,-6.8) V5(-3.6,-6.8) V6(-2.8,-6.8) V7(-2,-6.8) V8(-1.2,-6.8) V9(-0.4,-6.8) V10(0.4,-6.8) V11(1.2,-6.8) V12(2,-6.8) V13(2.8,-6.8) V14(3.6,-6.8) V15(4.4,-6.8) V16(5.2,-6.8) V17(6,-6.8) V18(6.8,-6.8)
BGA96_T9_P8_9X14
  round 0.356 smd: A1(-3.2,6.001) A2(-2.4,6.001) A3(-1.6,6.001) A7(1.6,6.001) A8(2.4,6.001) A9(3.2,6.001) B1(-3.2,5.201) B2(-2.4,5.201) B3(-1.6,5.201) B7(1.6,5.201) B8(2.4,5.201) B9(3.2,5.201) C1(-3.2,4.401) C2(-2.4,4.401) C3(-1.6,4.401) C7(1.6,4.401) C8(2.4,4.401) C9(3.2,4.401) D1(-3.2,3.6) D2(-2.4,3.6) D3(-1.6,3.6) D7(1.6,3.6) D8(2.4,3.6) D9(3.2,3.6) E1(-3.2,2.8) E2(-2.4,2.8) E3(-1.6,2.8) E7(1.6,2.8) E8(2.4,2.8) E9(3.2,2.8) F1(-3.2,2) F2(-2.4,2) F3(-1.6,2) F7(1.6,2) F8(2.4,2) F9(3.2,2) G1(-3.2,1.2) G2(-2.4,1.2) G3(-1.6,1.2) G7(1.6,1.2) G8(2.4,1.2) G9(3.2,1.2) H1(-3.2,0.4) H2(-2.4,0.4) H3(-1.6,0.4) H7(1.6,0.4) H8(2.4,0.4) H9(3.2,0.4) J1(-3.2,-0.4) J2(-2.4,-0.4) J3(-1.6,-0.4) J7(1.6,-0.4) J8(2.4,-0.4) J9(3.2,-0.4) K1(-3.2,-1.2) K2(-2.4,-1.2) K3(-1.6,-1.2) K7(1.6,-1.2) K8(2.4,-1.2) K9(3.2,-1.2) L1(-3.2,-2) L2(-2.4,-2) L3(-1.6,-2) L7(1.6,-2) L8(2.4,-2) L9(3.2,-2) M1(-3.2,-2.8) M2(-2.4,-2.8) M3(-1.6,-2.8) M7(1.6,-2.8) M8(2.4,-2.8) M9(3.2,-2.8) N1(-3.2,-3.6) N2(-2.4,-3.6) N3(-1.6,-3.6) N7(1.6,-3.6) N8(2.4,-3.6) N9(3.2,-3.6) P1(-3.2,-4.401) P2(-2.4,-4.401) P3(-1.6,-4.401) P7(1.6,-4.401) P8(2.4,-4.401) P9(3.2,-4.401) R1(-3.2,-5.201) R2(-2.4,-5.201) R3(-1.6,-5.201) R7(1.6,-5.201) R8(2.4,-5.201) R9(3.2,-5.201) T1(-3.2,-6.001) T2(-2.4,-6.001) T3(-1.6,-6.001) T7(1.6,-6.001) T8(2.4,-6.001) T9(3.2,-6.001)
BGA153_P14_P5_11P5X13
  round 0.254 smd: A1(-3.25,3.25) A2(-2.75,3.25) A3(-2.25,3.25) A4(-1.75,3.25) A5(-1.25,3.25) A6(-0.75,3.25) A7(-0.25,3.25) A8(0.25,3.25) A9(0.75,3.25) A10(1.25,3.25) A11(1.75,3.25) A12(2.25,3.25) A13(2.75,3.25) A14(3.25,3.25) B1(-3.25,2.75) B2(-2.75,2.75) B3(-2.25,2.75) B4(-1.75,2.75) B5(-1.25,2.75) B6(-0.75,2.75) B7(-0.25,2.75) B8(0.25,2.75) B9(0.75,2.75) B10(1.25,2.75) B11(1.75,2.75) B12(2.25,2.75) B13(2.75,2.75) B14(3.25,2.75) C1(-3.25,2.25) C2(-2.75,2.25) C3(-2.25,2.25) C4(-1.75,2.25) C5(-1.25,2.25) C6(-0.75,2.25) C7(-0.25,2.25) C8(0.25,2.25) C9(0.75,2.25) C10(1.25,2.25) C11(1.75,2.25) C12(2.25,2.25) C13(2.75,2.25) C14(3.25,2.25) D1(-3.25,1.75) D2(-2.75,1.75) D3(-2.25,1.75) D4(-1.75,1.75) D12(2.25,1.75) D13(2.75,1.75) D14(3.25,1.75) E1(-3.25,1.25) E2(-2.75,1.25) E3(-2.25,1.25) E5(-1.25,1.25) E6(-0.75,1.25) E7(-0.25,1.25) E8(0.25,1.25) E9(0.75,1.25) E10(1.25,1.25) E12(2.25,1.25) E13(2.75,1.25) E14(3.25,1.25) F1(-3.25,0.75) F2(-2.75,0.75) F3(-2.25,0.75) F5(-1.25,0.75) F10(1.25,0.75) F12(2.25,0.75) F13(2.75,0.75) F14(3.25,0.75) G1(-3.25,0.25) G2(-2.75,0.25) G3(-2.25,0.25) G5(-1.25,0.25) G10(1.25,0.25) G12(2.25,0.25) G13(2.75,0.25) G14(3.25,0.25) H1(-3.25,-0.25) H2(-2.75,-0.25) H3(-2.25,-0.25) H5(-1.25,-0.25) H10(1.25,-0.25) H12(2.25,-0.25) H13(2.75,-0.25) H14(3.25,-0.25) J1(-3.25,-0.75) J2(-2.75,-0.75) J3(-2.25,-0.75) J5(-1.25,-0.75) J10(1.25,-0.75) J12(2.25,-0.75) J13(2.75,-0.75) J14(3.25,-0.75) K1(-3.25,-1.25) K2(-2.75,-1.25) K3(-2.25,-1.25) K5(-1.25,-1.25) K6(-0.75,-1.25) K7(-0.25,-1.25) K8(0.25,-1.25) K9(0.75,-1.25) K10(1.25,-1.25) K12(2.25,-1.25) K13(2.75,-1.25) K14(3.25,-1.25) L1(-3.25,-1.75) L2(-2.75,-1.75) L3(-2.25,-1.75) L12(2.25,-1.75) L13(2.75,-1.75) L14(3.25,-1.75) M1(-3.25,-2.25) M2(-2.75,-2.25) M3(-2.25,-2.25) M4(-1.75,-2.25) M5(-1.25,-2.25) M6(-0.75,-2.25) M7(-0.25,-2.25) M8(0.25,-2.25) M9(0.75,-2.25) M10(1.25,-2.25) M11(1.75,-2.25) M12(2.25,-2.25) M13(2.75,-2.25) M14(3.25,-2.25) N1(-3.25,-2.75) N2(-2.75,-2.75) N3(-2.25,-2.75) N4(-1.75,-2.75) N5(-1.25,-2.75) N6(-0.75,-2.75) N7(-0.25,-2.75) N8(0.25,-2.75) N9(0.75,-2.75) N10(1.25,-2.75) N11(1.75,-2.75) N12(2.25,-2.75) N13(2.75,-2.75) N14(3.25,-2.75) P1(-3.25,-3.25) P2(-2.75,-3.25) P3(-2.25,-3.25) P4(-1.75,-3.25) P5(-1.25,-3.25) P6(-0.75,-3.25) P7(-0.25,-3.25) P8(0.25,-3.25) P9(0.75,-3.25) P10(1.25,-3.25) P11(1.75,-3.25) P12(2.25,-3.25) P13(2.75,-3.25) P14(3.25,-3.25)
DCK5_2P15X1P4
  rect 0.4x0.9 smd: 1(-0.65,-1.1) 2(0,-1.1) 3(0.65,-1.1) 4(0.65,1.1) 5(-0.65,1.1)
DFN2X2-6L
  rect 0.61x0.406 smd: 1(-0.9,0.65) 2(-0.9,0) 3(-0.9,-0.65) 4(0.9,-0.65) 5(0.9,0) 6(0.9,0.65)
  rect 0.61x1.27 smd: 7(0,0)
DFN2X2-8L
  rect 0.305x0.711 smd: 1(-0.75,-0.85) 2(-0.25,-0.85) 3(0.25,-0.85) 4(0.75,-0.85) 5(0.75,0.85) 6(0.25,0.85) 7(-0.25,0.85) 8(-0.75,0.85)
  rect 1.321x0.508 smd: 9(0,0)
E-13_4X13_3-N100_0_75-TOP
  rect 0.75x0.75 smd: 1(-6.025,-5.975) 17(6.025,-5.975) 33(6.025,5.975) 49(-6.025,5.975)
  rect 0.4x0.75 smd: 2(-4.9,-5.975) 3(-4.2,-5.975) 4(-3.5,-5.975) 5(-2.8,-5.975) 6(-2.1,-5.975) 7(-1.4,-5.975) 8(-0.7,-5.975) 9(0,-5.975) 10(0.7,-5.975) 11(1.4,-5.975) 12(2.1,-5.975) 13(2.8,-5.975) 14(3.5,-5.975) 15(4.2,-5.975) 16(4.9,-5.975) 34(4.9,5.975) 35(4.2,5.975) 36(3.5,5.975) 37(2.8,5.975) 38(2.1,5.975) 39(1.4,5.975) 40(0.7,5.975) 41(0,5.975) 42(-0.7,5.975) 43(-1.4,5.975) 44(-2.1,5.975) 45(-2.8,5.975) 46(-3.5,5.975) 47(-4.2,5.975) 48(-4.9,5.975)
  rect 0.75x0.4 smd: 18(6.025,-4.9) 19(6.025,-4.2) 20(6.025,-3.5) 21(6.025,-2.8) 22(6.025,-2.1) 23(6.025,-1.4) 24(6.025,-0.7) 25(6.025,0) 26(6.025,0.7) 27(6.025,1.4) 28(6.025,2.1) 29(6.025,2.8) 30(6.025,3.5) 31(6.025,4.2) 32(6.025,4.9) 50(-6.025,4.9) 51(-6.025,4.2) 52(-6.025,3.5) 53(-6.025,2.8) 54(-6.025,2.1) 55(-6.025,1.4) 56(-6.025,0.7) 57(-6.025,0) 58(-6.025,-0.7) 59(-6.025,-1.4) 60(-6.025,-2.1) 61(-6.025,-2.8) 62(-6.025,-3.5) 63(-6.025,-4.2) 64(-6.025,-4.9)
  rect 1x1 smd: G1(-3.85,-3.85) G2(-2.45,-3.85) G3(-1.05,-3.85) G4(-3.85,-2.45) G5(-2.45,-2.45) G6(-1.05,-2.45) G7(-3.85,-1.05) G8(-2.45,-1.05) G9(-1.05,-1.05) G10(1.05,-3.85) G11(2.45,-3.85) G12(3.85,-3.85) G13(1.05,-2.45) G14(2.45,-2.45) G15(3.85,-2.45) G16(1.05,-1.05) G17(2.45,-1.05) G18(3.85,-1.05) G19(-3.85,1.05) G20(-2.45,1.05) G21(-1.05,1.05) G22(-3.85,2.45) G23(-2.45,2.45) G24(-1.05,2.45) G25(-3.85,3.85) G26(-2.45,3.85) G27(-1.05,3.85) G28(1.05,1.05) G29(2.45,1.05) G30(3.85,1.05) G31(1.05,2.45) G32(2.45,2.45) G33(3.85,2.45) G34(1.05,3.85) G35(2.45,3.85) G36(3.85,3.85)
HEADER10X2_SMD
  rect 0.711x2.794 smd: 1(-5.715,-2.705) 2(-5.715,2.705) 3(-4.445,-2.705) 4(-4.445,2.705) 5(-3.175,-2.705) 6(-3.175,2.705) 7(-1.905,-2.705) 8(-1.905,2.705) 9(-0.635,-2.705) 10(-0.635,2.705) 11(0.635,-2.705) 12(0.635,2.705) 13(1.905,-2.705) 14(1.905,2.705) 15(3.175,-2.705) 16(3.175,2.705) 17(4.445,-2.705) 18(4.445,2.705) 19(5.715,-2.705) 20(5.715,2.705)
HEADER23X2
  rect 1.524x1.524 hole 0.889: 1(0,0)
  round 1.524 hole 0.889: 2(0,2.54) 3(2.54,0) 4(2.54,2.54) 5(5.08,0) 6(5.08,2.54) 7(7.62,0) 8(7.62,2.54) 9(10.16,0) 10(10.16,2.54) 11(12.7,0) 12(12.7,2.54) 13(15.24,0) 14(15.24,2.54) 15(17.78,0) 16(17.78,2.54) 17(20.32,0) 18(20.32,2.54) 19(22.86,0) 20(22.86,2.54) 21(25.4,0) 22(25.4,2.54) 23(27.94,0) 24(27.94,2.54) 25(30.48,0) 26(30.48,2.54) 27(33.02,0) 28(33.02,2.54) 29(35.56,0) 30(35.56,2.54) 31(38.1,0) 32(38.1,2.54) 33(40.64,0) 34(40.64,2.54) 35(43.18,0) 36(43.18,2.54) 37(45.72,0) 38(45.72,2.54) 39(48.26,0) 40(48.26,2.54) 41(50.8,0) 42(50.8,2.54) 43(53.34,0) 44(53.34,2.54) 45(55.88,0) 46(55.88,2.54)
LED_0603
  rect 0.762x1.016 smd: 1(-0.826,0) 2(0.826,0)
MTGH200C125D_PL
  round 4.445 hole 3.175: 1(0,0)
OSC4-SMD-2_5X2_0X0_55MM
  rect 1.219x1.016 smd: 1(-0.85,-0.7) 2(0.85,-0.7) 3(0.85,0.7) 4(-0.85,0.7)
OSC4_61X65LS_79X98SMD
  rect 0.711x0.889 smd: 1(-0.826,-0.775) 2(0.826,-0.775) 3(0.826,0.775) 4(-0.826,0.775)
QFN-28
  rect 0.914x0.254 smd: 1(-2.591,1.5) 2(-2.591,1) 3(-2.591,0.5) 4(-2.591,0) 5(-2.591,-0.5) 6(-2.591,-1) 7(-2.591,-1.5) 15(2.591,-1.5) 16(2.591,-1) 17(2.591,-0.5) 18(2.591,0) 19(2.591,0.5) 20(2.591,1) 21(2.591,1.5)
  rect 0.254x0.914 smd: 8(-1.5,-2.591) 9(-1,-2.591) 10(-0.5,-2.591) 11(0,-2.591) 12(0.5,-2.591) 13(1,-2.591) 14(1.5,-2.591) 22(1.5,2.591) 23(1,2.591) 24(0.5,2.591) 25(0,2.591) 26(-0.5,2.591) 27(-1,2.591) 28(-1.5,2.591)
  rect 3.251x3.251 smd: 29(0,0)
SD-MICRO-SCHA5B0300
  rect 0.914x0.457 smd: 1(-7.257,0) 2(-7.257,-0.7) 3(-7.257,-1.4) 4(-7.257,-2.1) 5(7.257,-2.1) 6(7.257,-1.4) 7(7.257,-0.7) 8(7.257,0)
  rect 0.508x0.889 smd: 9(3.775,9.989) 10(-5.975,9.989)
  rect 0.889x2.007 smd: 11(-7.25,7.635) 12(7.25,6.335)
  rect 1.118x1.524 smd: 13(-7.196,-3.365) 14(7.196,-3.365)
  rect 1.194x1.092 smd: 15(-3.425,10.488) 16(2.575,10.488)
SIP6
  rect 1.524x1.524 hole 1.016: 1(0,0)
  round 1.524 hole 1.016: 2(0,-2.54) 3(0,-5.08) 4(0,-7.62) 5(0,-10.16) 6(0,-12.7)
SM-7351-IND-0805
  rect 1.397x1.549 smd: 1(-0.95,0) 2(0.95,0)
SMINI6-F3-B
  rect 0.305x0.95 smd: 1(0.65,0.75) 2(0,0.75) 3(-0.65,0.75) 4(-0.65,-0.75) 5(0,-0.75) 6(0.65,-0.75)
SOT23-5
  rect 0.635x1.016 smd: 1(-0.953,-1.295) 2(0,-1.295) 3(0.953,-1.295) 4(0.953,1.295) 5(-0.953,1.295)
SOT-323-3
  rect 0.7x0.9 smd: 1(-0.65,-0.95) 2(0.65,-0.95) 3(0,0.95)
ST-USB-201C
  rect 1.321x1.321 hole 0.914: A1(3.5,-5.33)
  round 1.321 hole 0.914: A2(1,-5.33) A3(-1,-5.33) A4(-3.5,-5.33) B1(3.5,-2.71) B2(1,-2.71) B3(-1,-2.71) B4(-3.5,-2.71)
  round 2.946 hole 2.337: S1(6.57,-5.68) S2(-6.57,-5.68) S3(-6.57,0) S4(6.57,0)
SW_4P
  rect 1.422x0.813 smd: 1(-1.8,-0.94) 2(-1.8,0.94) 3(1.8,-0.94) 4(1.8,0.94)
TDFN8_P5_2P0
  rect 1.219x0.61 smd: (0,0)
  rect 0.305x0.711 smd: 1(-0.75,-0.85) 2(-0.25,-0.85) 3(0.25,-0.85) 4(0.75,-0.85) 5(0.75,0.85) 6(0.25,0.85) 7(-0.25,0.85) 8(-0.75,0.85)
TP1-8040
  round 1.524 hole 1.016: 1(0,0)
TP30C_SMD
  round 0.762 smd: 1(0,0)
TP60C33D
  round 1.524 hole 0.889: 1(0,0)
TP60C_SMD
  round 1.27 smd: 1(0,0)
U-FL3P-SMD-2_6X2_6X1_0MM
  rect 1.016x1.016 smd: 1(1.575,0)
  rect 2.235x1.016 smd: 2(0,1.475) 3(0,-1.475)
U_8_DCU
  rect 0.254x1.27 smd: 1(-0.749,-1.473) 2(-0.249,-1.473) 3(0.249,-1.473) 4(0.749,-1.473) 5(0.749,1.473) 6(0.249,1.473) 7(-0.249,1.473) 8(-0.749,1.473)
U_48_RSL
  rect 0.8x0.2 smd: 1(-3.075,2.2) 2(-3.075,1.8) 3(-3.075,1.4) 4(-3.075,1) 5(-3.075,0.6) 6(-3.075,0.2) 7(-3.075,-0.2) 8(-3.075,-0.6) 9(-3.075,-1) 10(-3.075,-1.4) 11(-3.075,-1.8) 12(-3.075,-2.2) 25(3.075,-2.2) 26(3.075,-1.8) 27(3.075,-1.4) 28(3.075,-1) 29(3.075,-0.6) 30(3.075,-0.2) 31(3.075,0.2) 32(3.075,0.6) 33(3.075,1) 34(3.075,1.4) 35(3.075,1.8) 36(3.075,2.2)
  rect 0.2x0.8 smd: 13(-2.2,-3.075) 14(-1.8,-3.075) 15(-1.4,-3.075) 16(-1,-3.075) 17(-0.6,-3.075) 18(-0.2,-3.075) 19(0.2,-3.075) 20(0.6,-3.075) 21(1,-3.075) 22(1.4,-3.075) 23(1.8,-3.075) 24(2.2,-3.075) 37(2.2,3.075) 38(1.8,3.075) 39(1.4,3.075) 40(1,3.075) 41(0.6,3.075) 42(0.2,3.075) 43(-0.2,3.075) 44(-0.6,3.075) 45(-1,3.075) 46(-1.4,3.075) 47(-1.8,3.075) 48(-2.2,3.075)
  rect 4.05x4.05 smd: 49(-0.225,0.225)
unnamed
  round 1.016 smd: 1(0,0)
unnamed#3
  round 2.032 hole 2.032 unplated: (0,0)
VQFN-20
  rect 0.914x0.254 smd: 1(-2.3,-0.75) 10(2.3,-0.75) 11(2.3,0.75) 20(-2.3,0.75)
  rect 0.254x0.914 smd: 2(-1.75,-1.8) 3(-1.25,-1.8) 4(-0.75,-1.8) 5(-0.25,-1.8) 6(0.25,-1.8) 7(0.75,-1.8) 8(1.25,-1.8) 9(1.75,-1.8) 12(1.75,1.8) 13(1.25,1.8) 14(0.75,1.8) 15(0.25,1.8) 16(-0.25,1.8) 17(-0.75,1.8) 18(-1.25,1.8) 19(-1.75,1.8)
  custom 0.512x0.512 smd: 21(0,0)
X4-SMD-3_2X2_5X1_0MM
  rect 1.321x1.067 smd: 1(-1.15,-0.925) 2(1.15,-0.925) 3(1.15,0.925) 4(-1.15,0.925)
XTAL4_126-216SMD
  rect 1.27x1.905 smd: 1(-2.748,-1.6) 2(2.751,-1.6) 3(2.751,1.6) 4(-2.748,1.6)
XTAL150SMD_125X196
  rect 1.778x2.159 smd: 1(-1.9,0) 2(1.9,0)

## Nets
DGND: ANT.2(GND#2) ANT.3(GND#3) C1.1 C2.1 C3.1 C4.1 C7.1 C8.1 C9.1 C10.1 C11.1 C12.1 C13.1 C14.1 C15.1 C16.2 C18.2 C24.2 C28.2 C29.2 C30.2 C36.2 C37.2 C38.2 C39.1 C40.1 C41.2 C42.2 C43.2 C44.2 C45.2 C46.2 C47.2 C48.2 C49.2 C50.2 C51.2 C52.2 C53.2 C54.2 C55.1 C56.1 C57.1 C58.2 C59.2 C60.1 C61.1 C62.1 C63.2 C64.2 C65.2 C66.2 C67.2 C68.1 C69.1 C70.1 C71.1 C72.1 C73.1 C74.1 C75.1 C76.1 C77.2 C78.2 C79.2 C80.2 C81.2 C82.2 C83.2 C84.2 C85.2 C86.2 C87.2 C88.2 C89.2 C90.2 C91.2 C92.2 C94.2 C95.1 C96.1 C97.2 C98.2 C99.2 C100.2 C101.2 C102.2 C103.2 C104.2 C105.2 C106.2 C107.2 C108.2 C109.2 C110.2 C111.2 C112.2 C113.2 C114.2 C115.2 C116.2 C117.2 C118.1 C119.2 C120.2 C121.2 C122.1 C123.2 C124.2 C125.2 C126.1 C127.2 C128.2 C129.2 C130.2 C152.2 C153.2 C154.2 C155.1 C158.2 C159.2 C167.2 C168.1 C169.1 C170.1 C173.2 C174.2 C175.1 C176.1 C177.1 C178.1 C179.1 C180.1 C181.2 C182.2 C183.2 C184.2 C185.2 C186.1 C187.2 C188.2 C189.2 C190.2 C191.2 C192.2 C193.2 C194.2 C195.2 C196.2 C197.2 C198.2 C199.2 C202.2 C203.2 C204.2 C205.2 D9.2 D10.2 D11.2 D12.1 D13.1 D14.1 D15.2 D16.2 D17.2 D18.1 D19.1 D20.1 D21.1 D22.1 D23.1 D24.1 FB3.2 J1.1 J4.4 J5.4 J6.2(SHIELD1) J6.3(SHIELD2) J7.2(SHIELD1) J7.3(SHIELD2) J8.A4(GND_T) J8.B4(GND_B) J8.S1 J8.S2 J8.S3 J8.S4 J9.A4(GND_T) J9.B4(GND_B) J9.S1 J9.S2 J9.S3 J9.S4 L7.1 L8.1 L9.1 L10.1 L21.1 L22.1 OSC1.2(GND) P2.4(TDIS) P2.8(GND1) P2.10(GND2) P2.12(GND3) P2.16(GND4) P2.20(GND5) P4.5(G1) P4.6(G3) P4.7(G2) P4.8(G5) P4.9(G4) P8.1 P8.2(26) P9.1 P9.2(26) P9.43(22) P9.44(47) P9.45(23) P9.46(48) P10.6(VSS) P10.9(GND) P10.11(GND3) P10.12(GND4) P10.13(GND5) P10.14(GND6) P10.15(GND7) P10.16(GND8) Q1.1(4) Q1.4 Q2.1(4) Q2.4 Q3.2(SOURCE) Q4.2(SOURCE) R12.1 R22.1 R25.2 R29.1 R30.1 R49.1 R54.1 R76.2 R77.2 R78.2 R79.2 R80.2 R81.2 R82.2 R83.2 R84.2 R85.2 R86.2 R87.2 R88.2 R89.2 R90.2 R91.2 R92.2 R93.2 R94.2 R95.2 R96.1 R99.2 R100.2 R164.2 R165.2 R170.2 R189.2 R190.2 R197.2 R209.2 R210.2 R215.2 R217.2 R218.2 R221.1 R222.1 R226.1 R228.1 S1.1(A1) S1.3(A2) S2.2(B1) S2.4(B2) S3.1(A1) S3.3(A2) TP1.1(TP) TP8.1(TP) U2.30(PGND) U2.41(AGND) U2.49(PPAD) U3.3(GND) U5.A1(VSS1) U5.A18(VSS2) U5.F8(VSS3) U5.G8(VSS4) U5.G9(VSS5) U5.G11(VSS6) U5.G12(VSS7) U5.H6(VSS8) U5.H7(VSS9) U5.H8(VSS10) U5.H9(VSS11) U5.H10(VSS12) U5.H12(VSS13) U5.J6(VSS14) U5.J7(VSS15) U5.J8(VSS16) U5.J9(VSS17) U5.J10(VSS18) U5.J11(VSS19) U5.K7(VSS20) U5.K9(VSS21) U5.K10(VSS22) U5.K11(VSS23) U5.L10(VSS24) U5.L11(VSS25) U5.L12(VSS26) U5.L13(VSS27) U5.M6(VSS28) U5.M7(VSS29) U5.M8(VSS30) U5.M9(VSS31) U5.M10(VSS32) U5.M12(VSS33) U5.M14(VSSA_USB2) U5.N7(VSS34) U5.N10(VSS35) U5.N11(VSS36) U5.N14(VSSA_USB1) U5.V1(VSS37) U5.V18(VSS38) U7.2(VSS) U12.A9(VSS1) U12.B1(VSSQ1) U12.B3(VSS2) U12.B9(VSSQ2) U12.D1(VSSQ3) U12.D8(VSSQ4) U12.E1(VSS3) U12.E2(VSSQ5) U12.E8(VSSQ6) U12.F9(VSSQ7) U12.G1(VSSQ8) U12.G8(VSS4) U12.G9(VSSQ9) U12.J2(VSS5) U12.J8(VSS6) U12.M1(VSS7) U12.M9(VSS8) U12.P1(VSS9) U12.P9(VSS10) U12.T1(VSS11) U12.T9(VSS12) U13.C4(VSSQ4) U13.E7(VSS2) U13.G5(VSS1) U13.H10(VSS3) U13.K8(VSS4) U13.N2(VSSQ1) U13.N5(VSS5) U13.P4(VSSQ3) U13.P6(VSSQ2) U15.1(1\O\E\) U15.4(GND) U16.3(GND) U18.1(GND#1) U18.7(GND#7) U18.9(GND#9) U18.15(GND#15) U18.16(GND#16) U18.17(GND#17) U18.19(GND#19) U18.20(GND#20) U18.23(GND#23) U18.24(GND#24) U18.28(GND#28) U18.29(GND#29) U18.30(GND#30) U18.31(GND#31) U18.33(GND#33) U18.34(GND#34) U18.35(GND#35) U18.37(GND#37) U18.39(GND#39) U18.44(GND#44) U18.45(GND#45) U18.48(GND#48) U18.49(GND#49) U18.54(GND#54) U18.55(GND#55) U18.59(GND#59) U18.61(GND#61) U18.63(GND#63) U18.64(GND#64) U18.G1(GND#G1) U18.G2(GND#G2) U18.G3(GND#G3) U18.G4(GND#G4) U18.G5(GND#G5) U18.G6(GND#G6) U18.G7(GND#G7) U18.G8(GND#G8) U18.G9(GND#G9) U18.G10(GND#G10) U18.G11(GND#G11) U18.G12(GND#G12) U18.G13(GND#G13) U18.G14(GND#G14) U18.G15(GND#G15) U18.G16(GND#G16) U18.G17(GND#G17) U18.G18(GND#G18) U18.G19(GND#G19) U18.G20(GND#G20) U18.G21(GND#G21) U18.G22(GND#G22) U18.G23(GND#G23) U18.G24(GND#G24) U18.G25(GND#G25) U18.G26(GND#G26) U18.G27(GND#G27) U18.G28(GND#G28) U18.G29(GND#G29) U18.G30(GND#G30) U18.G31(GND#G31) U18.G32(GND#G32) U18.G33(GND#G33) U18.G34(GND#G34) U18.G35(GND#G35) U18.G36(GND#G36) U19.1(AGND) U19.3(PGND) U19.6(MODE) U19.9(GPAD) U20.1(AGND) U20.3(PGND) U20.6(MODE) U20.9(GPAD) U21.11(GND) U21.21(GPAD) U22.11(GND) U22.21(GPAD) U23.29(PAD) U24.5(GND) U24.7(PAD) Y4.2(GND) Y5.2 Y5.4
GND_EARTH: MTG1.1(TP) MTG3.1(TP) MTG4.1(TP)
GND_OSC0: C25.2 C26.2 R29.2 R173.2 R174.2 U5.V11(VSS_OSC0) U17.4(GND)
GND_OSC1: C21.1 C22.1 R30.2 U5.A5(VSS_RTC)
GNDA_ADC: C31.2 C32.2 C33.2 C93.2 FB3.1 P9.34(42) U5.A9(VREFN) U5.E8(VSSA_ADC)
VDD_1V8: C14.2 C78.1 C86.1 C88.1 FB1.1 FB2.2 R9.2 U2.40(LDO3) U5.D10(VDDS_SRAM_MPU_BB) U5.E9(VDDS_SRAM_CORE_BG) U5.N16(VDDA1P8V_USB0) U5.R16(VDDA1P8V_USB1)
VDD_1V8_WIFI: C168.2 C173.1 C174.1 C178.2 L4.2 L11.2 R191.1 R192.1 R193.1 R194.1 R195.1 R196.1 R214.1 R233.1 U18.38(VIO) U21.2(VCCA) U22.2(VCCA)
VDD_3V3_WIFI: C169.2 C170.2 C175.2 C176.2 L14.2 R229.1 R230.1 U18.46(VBAT#46) U18.47(VBAT#47) U21.19(VCCB) U22.19(VCCB)
VDD_3V3A: C15.2 C37.1 C38.1 C56.2 C57.2 C58.1 C59.1 C60.2 C61.2 C66.1 C67.1 C68.2 C69.2 C70.2 C71.2 C72.2 C73.2 C74.2 C75.2 C76.2 C77.1 C87.1 C152.1 C158.1 C159.1 R1.1 R3.1 R4.1 R14.1 R55.1 R56.1 R57.1 R58.1 R59.1 R60.1 R61.1 R62.1 R63.1 R64.1 R65.1 R66.1 R67.1 R68.1 R69.1 R70.1 R156.1 R169.2 R171.1 R172.1 R175.1 R223.2 U2.43(LDO4) U3.5(VCC) U5.E10(VDDSHV61) U5.E11(VDDSHV62) U5.E12(VDDSHV63) U5.E13(VDDSHV64) U5.F14(VDDSHV65) U5.G14(VDDSHV66) U5.H14(VDDSHV41) U5.J14(VDDSHV42) U5.K14(VDDSHV51) U5.L14(VDDSHV52) U5.N5(VDDSHV67) U5.N15(VDDA3P3V_USB0) U5.P5(VDDSHV68) U5.P6(VDDSHV69) U5.P7(VDDSHV11) U5.P8(VDDSHV12) U5.P10(VDDSHV21) U5.P11(VDDSHV22) U5.P12(VDDSHV31) U5.P13(VDDSHV32) U5.R15(VDDA3P3V_USB1) U7.4(VCC) U17.8(VDD) U20.5(EN) Y4.4(VCC)
VDD_3V3AUX: C18.1 D1.2(A) U2.1(VLDO2)
VDD_3V3B: C29.1 C126.2 C127.1 C128.1 C129.1 C130.1 C153.1 C154.1 C155.2 C179.2 L12.2 L14.1 P2.5(TVDD) P9.3(2) P9.4(27) P10.4(VDD) R23.1 R24.1 R101.1 R102.1 R103.1 R104.1 R105.1 R106.1 R107.1 R108.1 R109.1 R110.1 R111.1 R150.1 R151.1 R152.1 R153.1 R154.1 R155.1 R157.2 R163.1 R216.1 R231.2 R232.2 U13.C6(VCCQ4) U13.E6(VCC3) U13.F5(VCC2) U13.J10(VCC0) U13.K9(VCC1) U13.M4(VCCQ5) U13.N4(VCCQ3) U13.P3(VCCQ1) U13.P5(VCCQ2) U15.7(2OE) U15.8(VCC)
VDD_5V: C2.2 P9.5(3) P9.6(28) R168.2 U2.10(AC)
VDD_ADC: C93.1 FB2.1 P9.32(41) R27.1 U5.D8(VDDA_ADC)
VDD_CORE: C11.2 C39.2 C40.2 C41.1 C42.1 C43.1 C44.1 C45.1 C46.1 C47.1 C48.1 C49.1 C50.1 C51.1 C52.1 C53.1 C54.1 C55.2 L3.2 U2.29(VDCDC3) U5.F6(VDD_CORE1) U5.F7(VDD_CORE2) U5.G6(VDD_CORE3) U5.G7(VDD_CORE4) U5.G10(VDD_CORE5) U5.H11(VDD_CORE6) U5.J12(VDD_CORE7) U5.K6(VDD_CORE8) U5.K8(VDD_CORE9) U5.K12(VDD_CORE10) U5.L6(VDD_CORE11) U5.L7(VDD_CORE12) U5.L8(VDD_CORE13) U5.L9(VDD_CORE14) U5.M11(VDD_CORE15) U5.M13(VDD_CORE16) U5.N8(VDD_CORE17) U5.N9(VDD_CORE18) U5.N12(VDD_CORE19) U5.N13(VDD_CORE20)
VDD_MPU: C12.2 C62.2 C63.1 C64.1 C65.1 L2.2 U2.24(VDCDC2) U5.F10(VDD_MPU1) U5.F11(VDD_MPU2) U5.F12(VDD_MPU3) U5.F13(VDD_MPU4) U5.G13(VDD_MPU5) U5.H13(VDD_MPU6) U5.J13(VDD_MPU7)
VDD_MPUON: TP2.1(TP) U5.A2(VDD_MPU_MON)
VDD_PLL: C79.1 C92.1 C94.1 C106.1 FB1.2 U5.E7(VDDS_PLL_DDR) U5.H15(VDDS_PLL_MPU) U5.R10(VDDS_PLL_CORE_LCD) U5.R11(VDDS_OSC)
VDD_RTC: C104.1 U5.D6(CAP_VDD_RTC)
VDDS: C80.1 C81.1 C82.1 C83.1 C84.1 C85.1 R8.2 R9.1 U5.E6(VDDS1) U5.E14(VDDS2) U5.F9(VDDS3) U5.K13(VDDS4) U5.N6(VDDS5) U5.P9(VDDS6) U5.P14(VDDS7)
VDDS_DDR: C9.2 C95.2 C96.2 C97.1 C98.1 C99.1 C100.1 C101.1 C102.1 C103.1 C107.1 C108.1 C109.1 C110.1 C111.1 C112.1 C113.1 C114.1 C115.1 C116.1 C117.1 C118.2 C119.1 C120.1 C121.1 C122.2 R6.2 R97.1 R98.1 U5.E5(VDDS_DDR1) U5.F5(VDDS_DDR2) U5.G5(VDDS_DDR3) U5.H5(VDDS_DDR4) U5.J5(VDDS_DDR5) U5.K5(VDDS_DDR6) U5.L5(VDDS_DDR7) U12.A1(VDDQ1) U12.A8(VDDQ2) U12.B2(VDD1) U12.C1(VDDQ3) U12.C9(VDDQ4) U12.D2(VDDQ5) U12.D9(VDD9) U12.E9(VDDQ7) U12.F1(VDDQ8) U12.G7(VDD2) U12.H2(VDDQ9) U12.H9(VDDQ10) U12.K2(VDD4) U12.K8(VDD5) U12.N1(VDD6) U12.N9(VDD7) U12.R1(VDD8) U12.R9(VDD3)
AIN0: P9.39(20) U5.B6(AIN0)
AIN1: P9.40(45) U5.C7(AIN1)
AIN2: P9.37(19) U5.B7(AIN2)
AIN3: P9.38(44) U5.A7(AIN3)
AIN4: P9.33(17) U5.C8(AIN4)
AIN5: P9.36(43) U5.B8(AIN5)
AIN6: P9.35(18) U5.A8(AIN6)
AIN7: R163.2 R164.1 U5.C9(AIN7)
B_UART0_RX: J1.4 R165.1 U15.2(1A)
B_UART0_TX: J1.5 U15.3(2Y)
BT_AUD_CLK: TP13.1(TP) U18.60(BT_AUD_CLK) U21.1(A1)
BT_AUD_FSYNC: TP12.1(TP) U18.58(BT_AUD_FSYNC) U21.3(A2)
BT_AUD_IN: TP10.1(TP) U18.56(BT_AUD_IN) U21.5(A4)
BT_AUD_OUT: TP11.1(TP) U18.57(BT_AUD_OUT) U21.4(A3)
BT_EN: Q3.1(GATE) R188.1 U18.41(BT_EN_SOC)
BT_HCI_CTS: R184.1 U21.8(A7)
BT_HCI_RTS: R183.1 U21.9(A8)
BT_HCI_RX: R186.1 U21.6(A5)
BT_HCI_TX: R185.1 U21.7(A6)
CAP_VBB_MPU: C91.1 U5.C10(CAP_VBB_MPU)
CAP_VDD_SRAM_CORE: C89.1 U5.D9(CAP_VDD_SRAM_CORE)
